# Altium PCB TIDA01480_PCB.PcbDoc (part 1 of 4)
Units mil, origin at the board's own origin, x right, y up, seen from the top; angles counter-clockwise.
Board outline 2500 x 3500 mil, 6 copper layers (Top Layer, GND Upper, Signal Layer 1, Signal Layer 2, GND Lower, Bottom Layer), stack 63.4 mil thick; 332 components, 140 nets, 983 pads, 692 vias.
Unrouted connection lines stored in the file: 17.
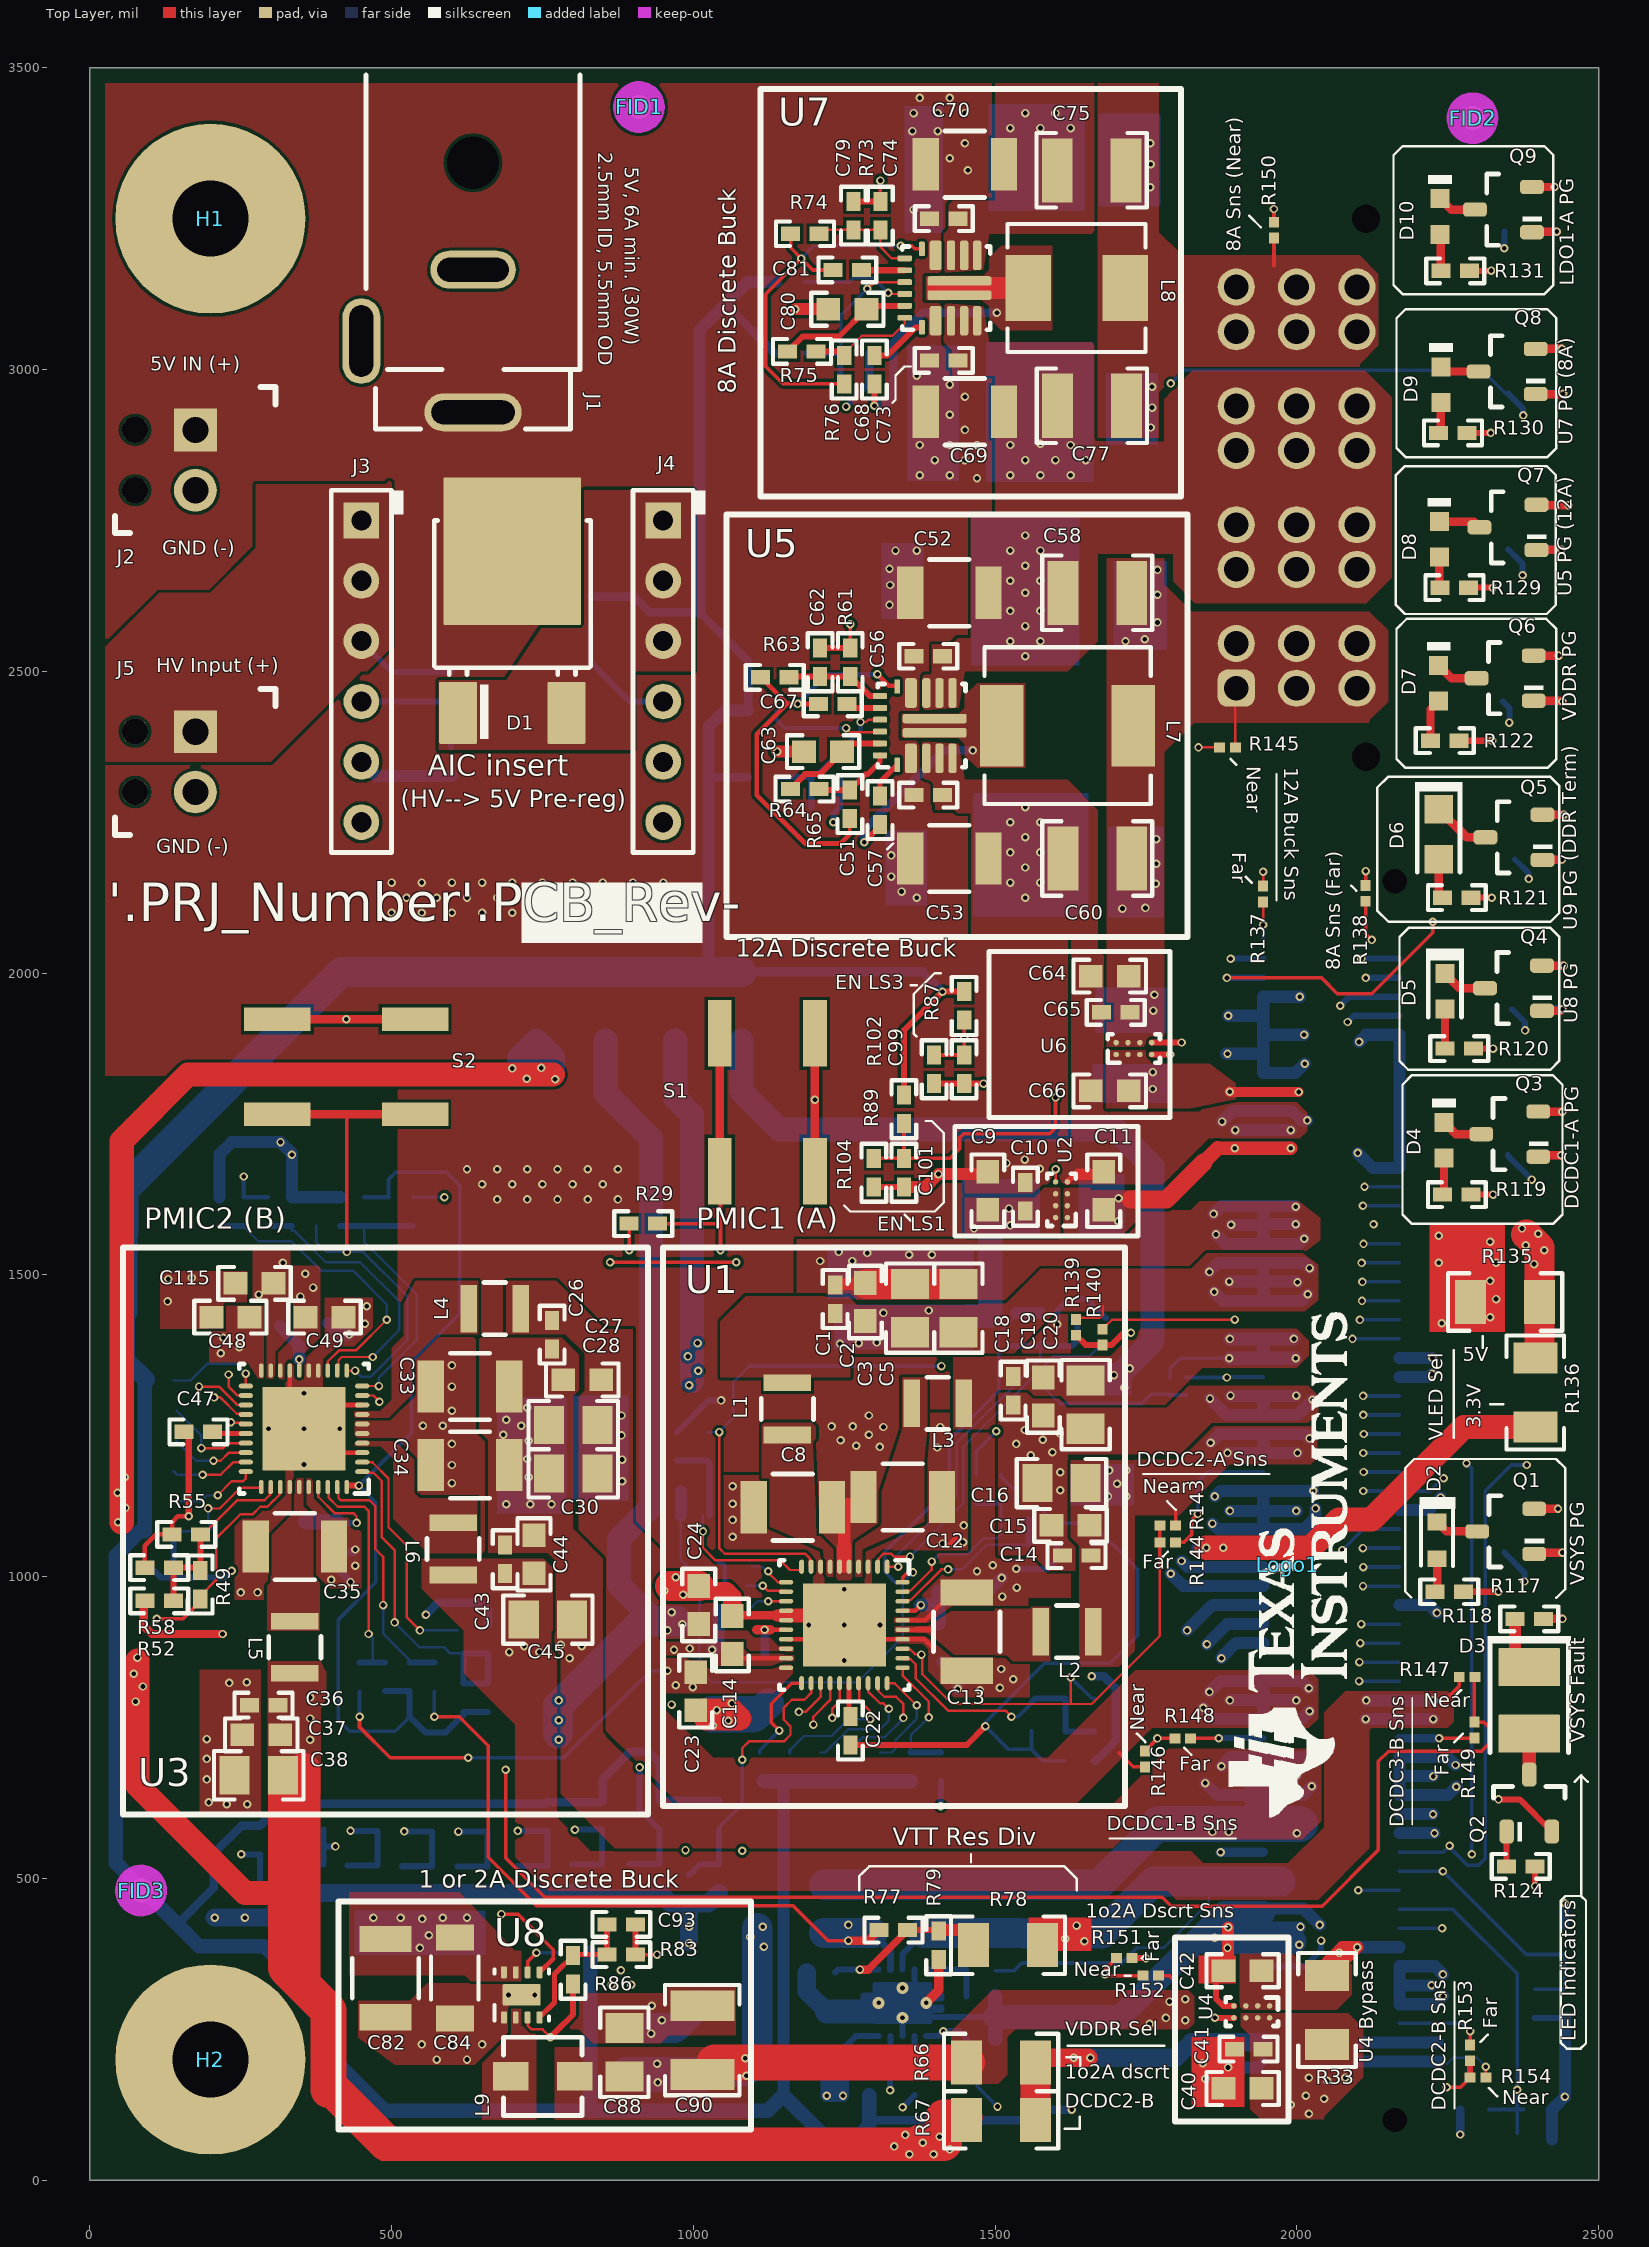
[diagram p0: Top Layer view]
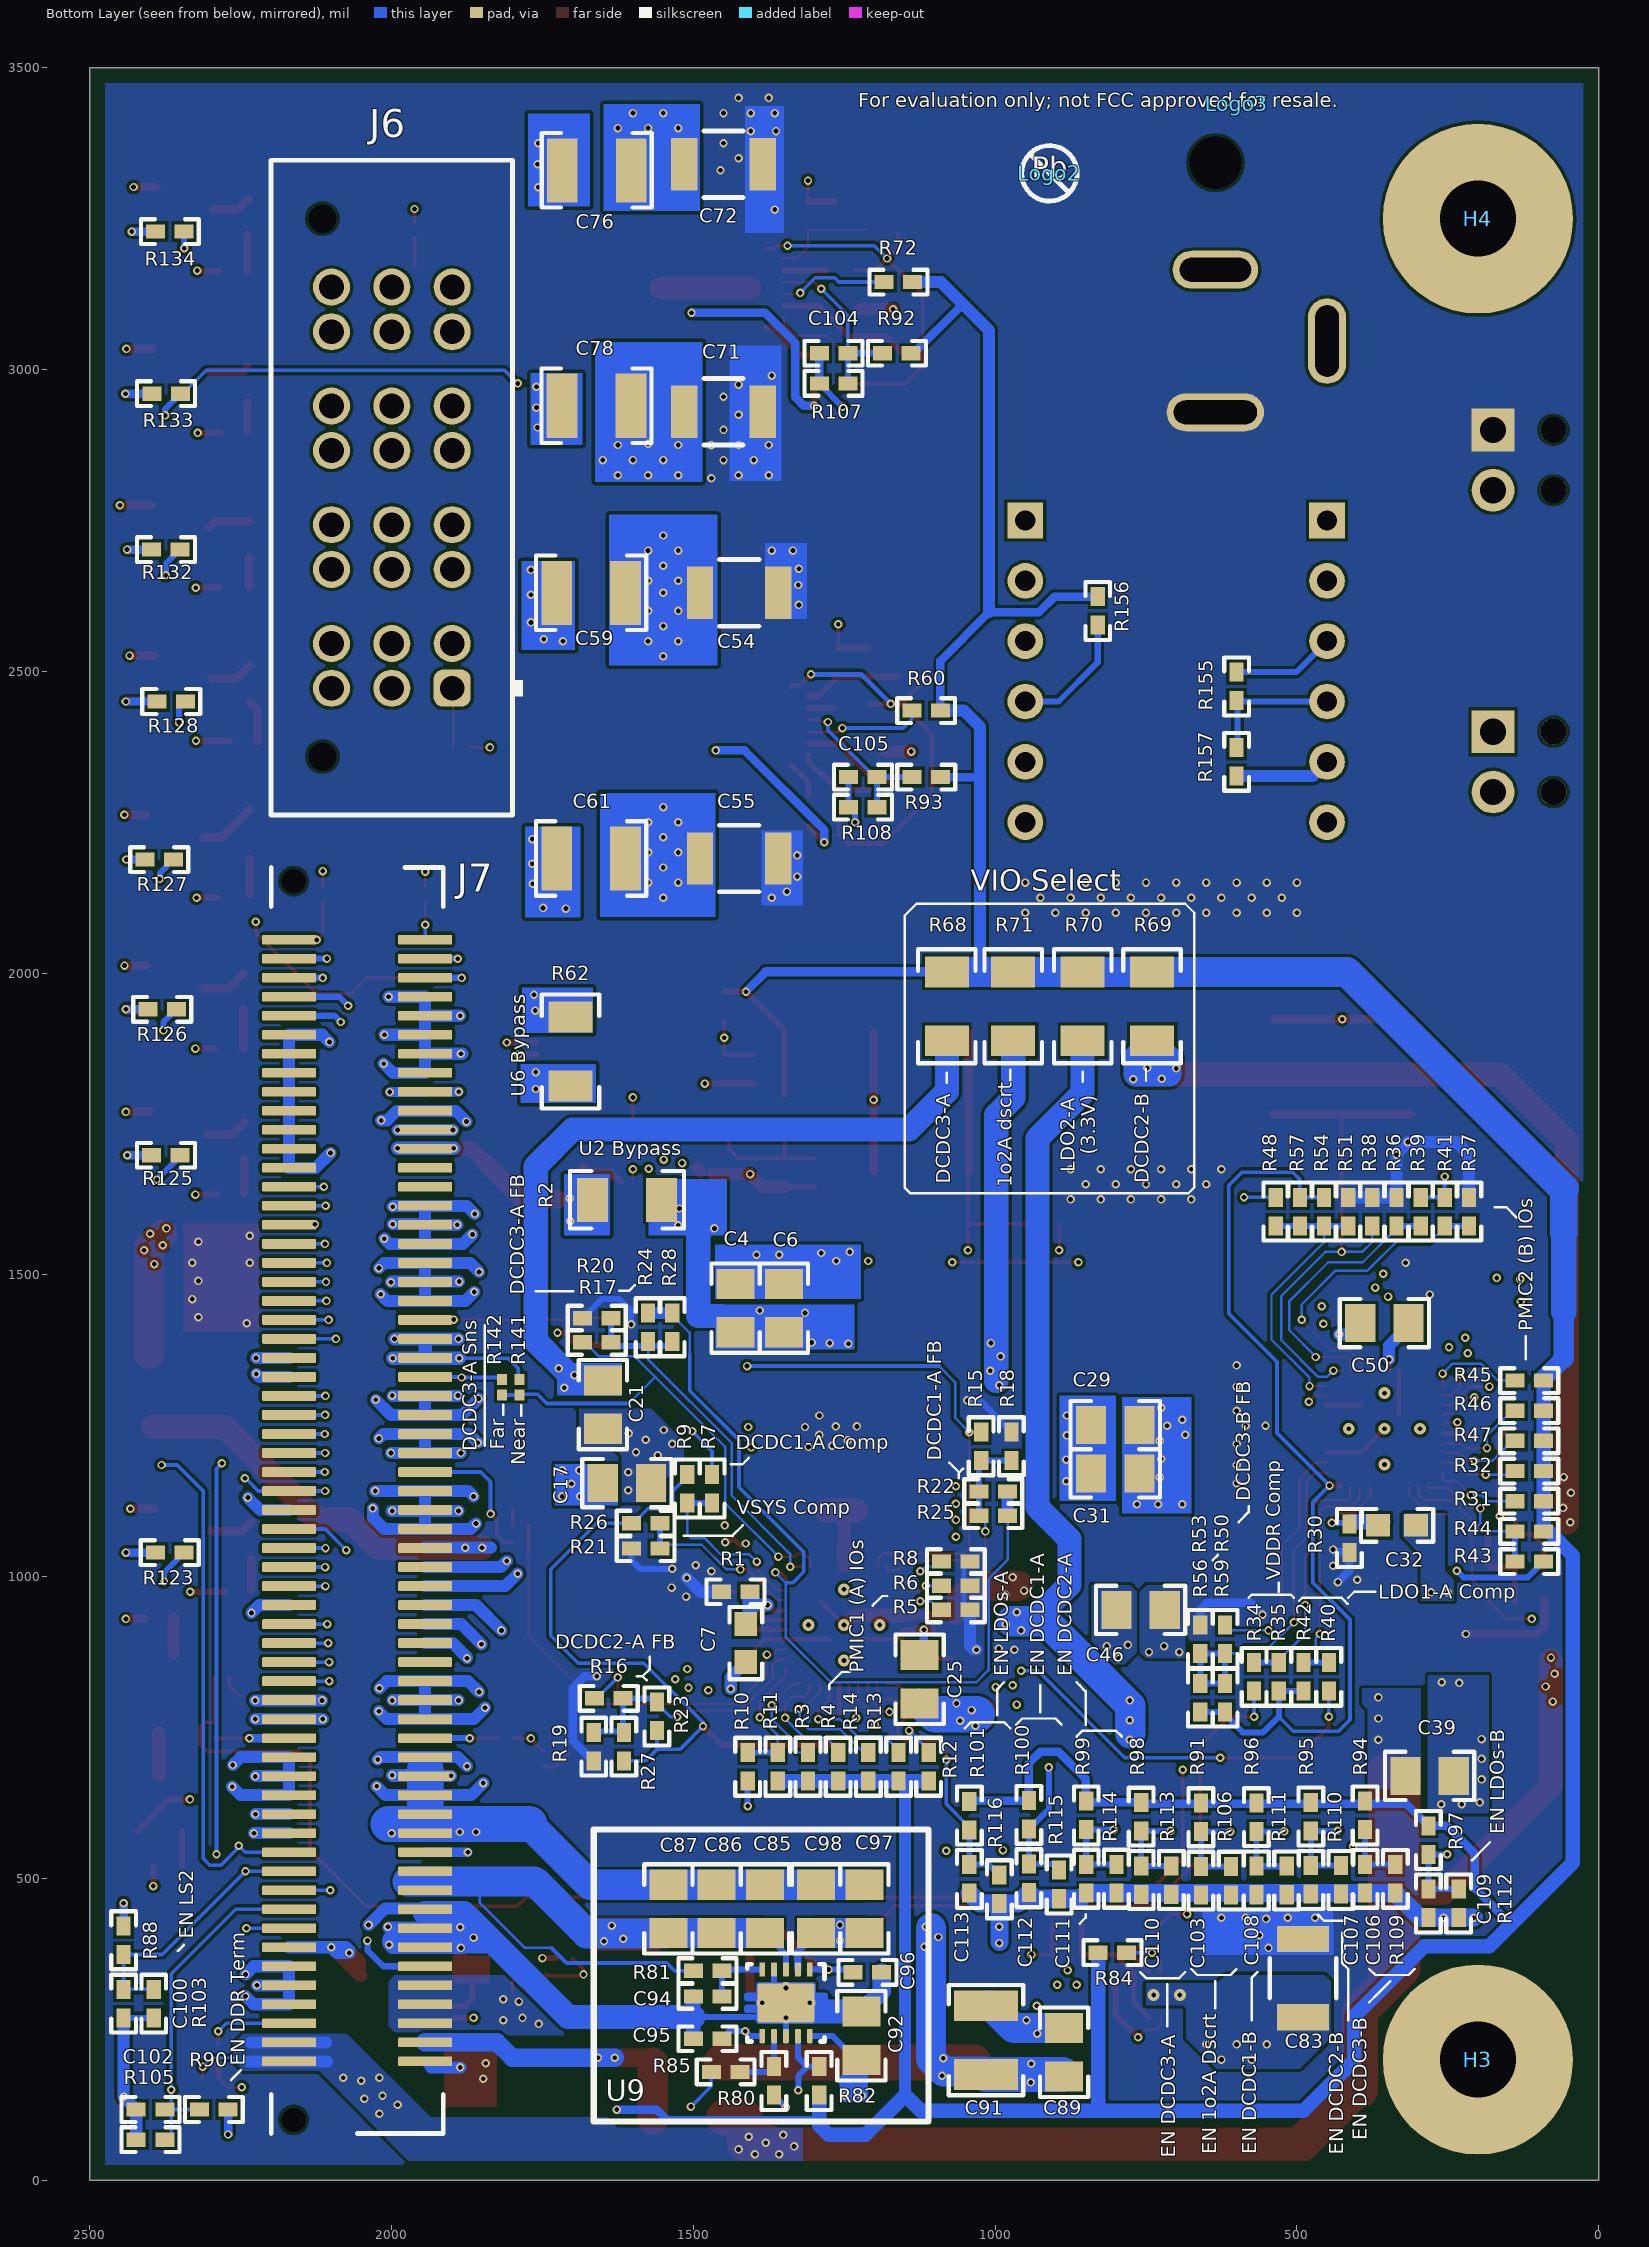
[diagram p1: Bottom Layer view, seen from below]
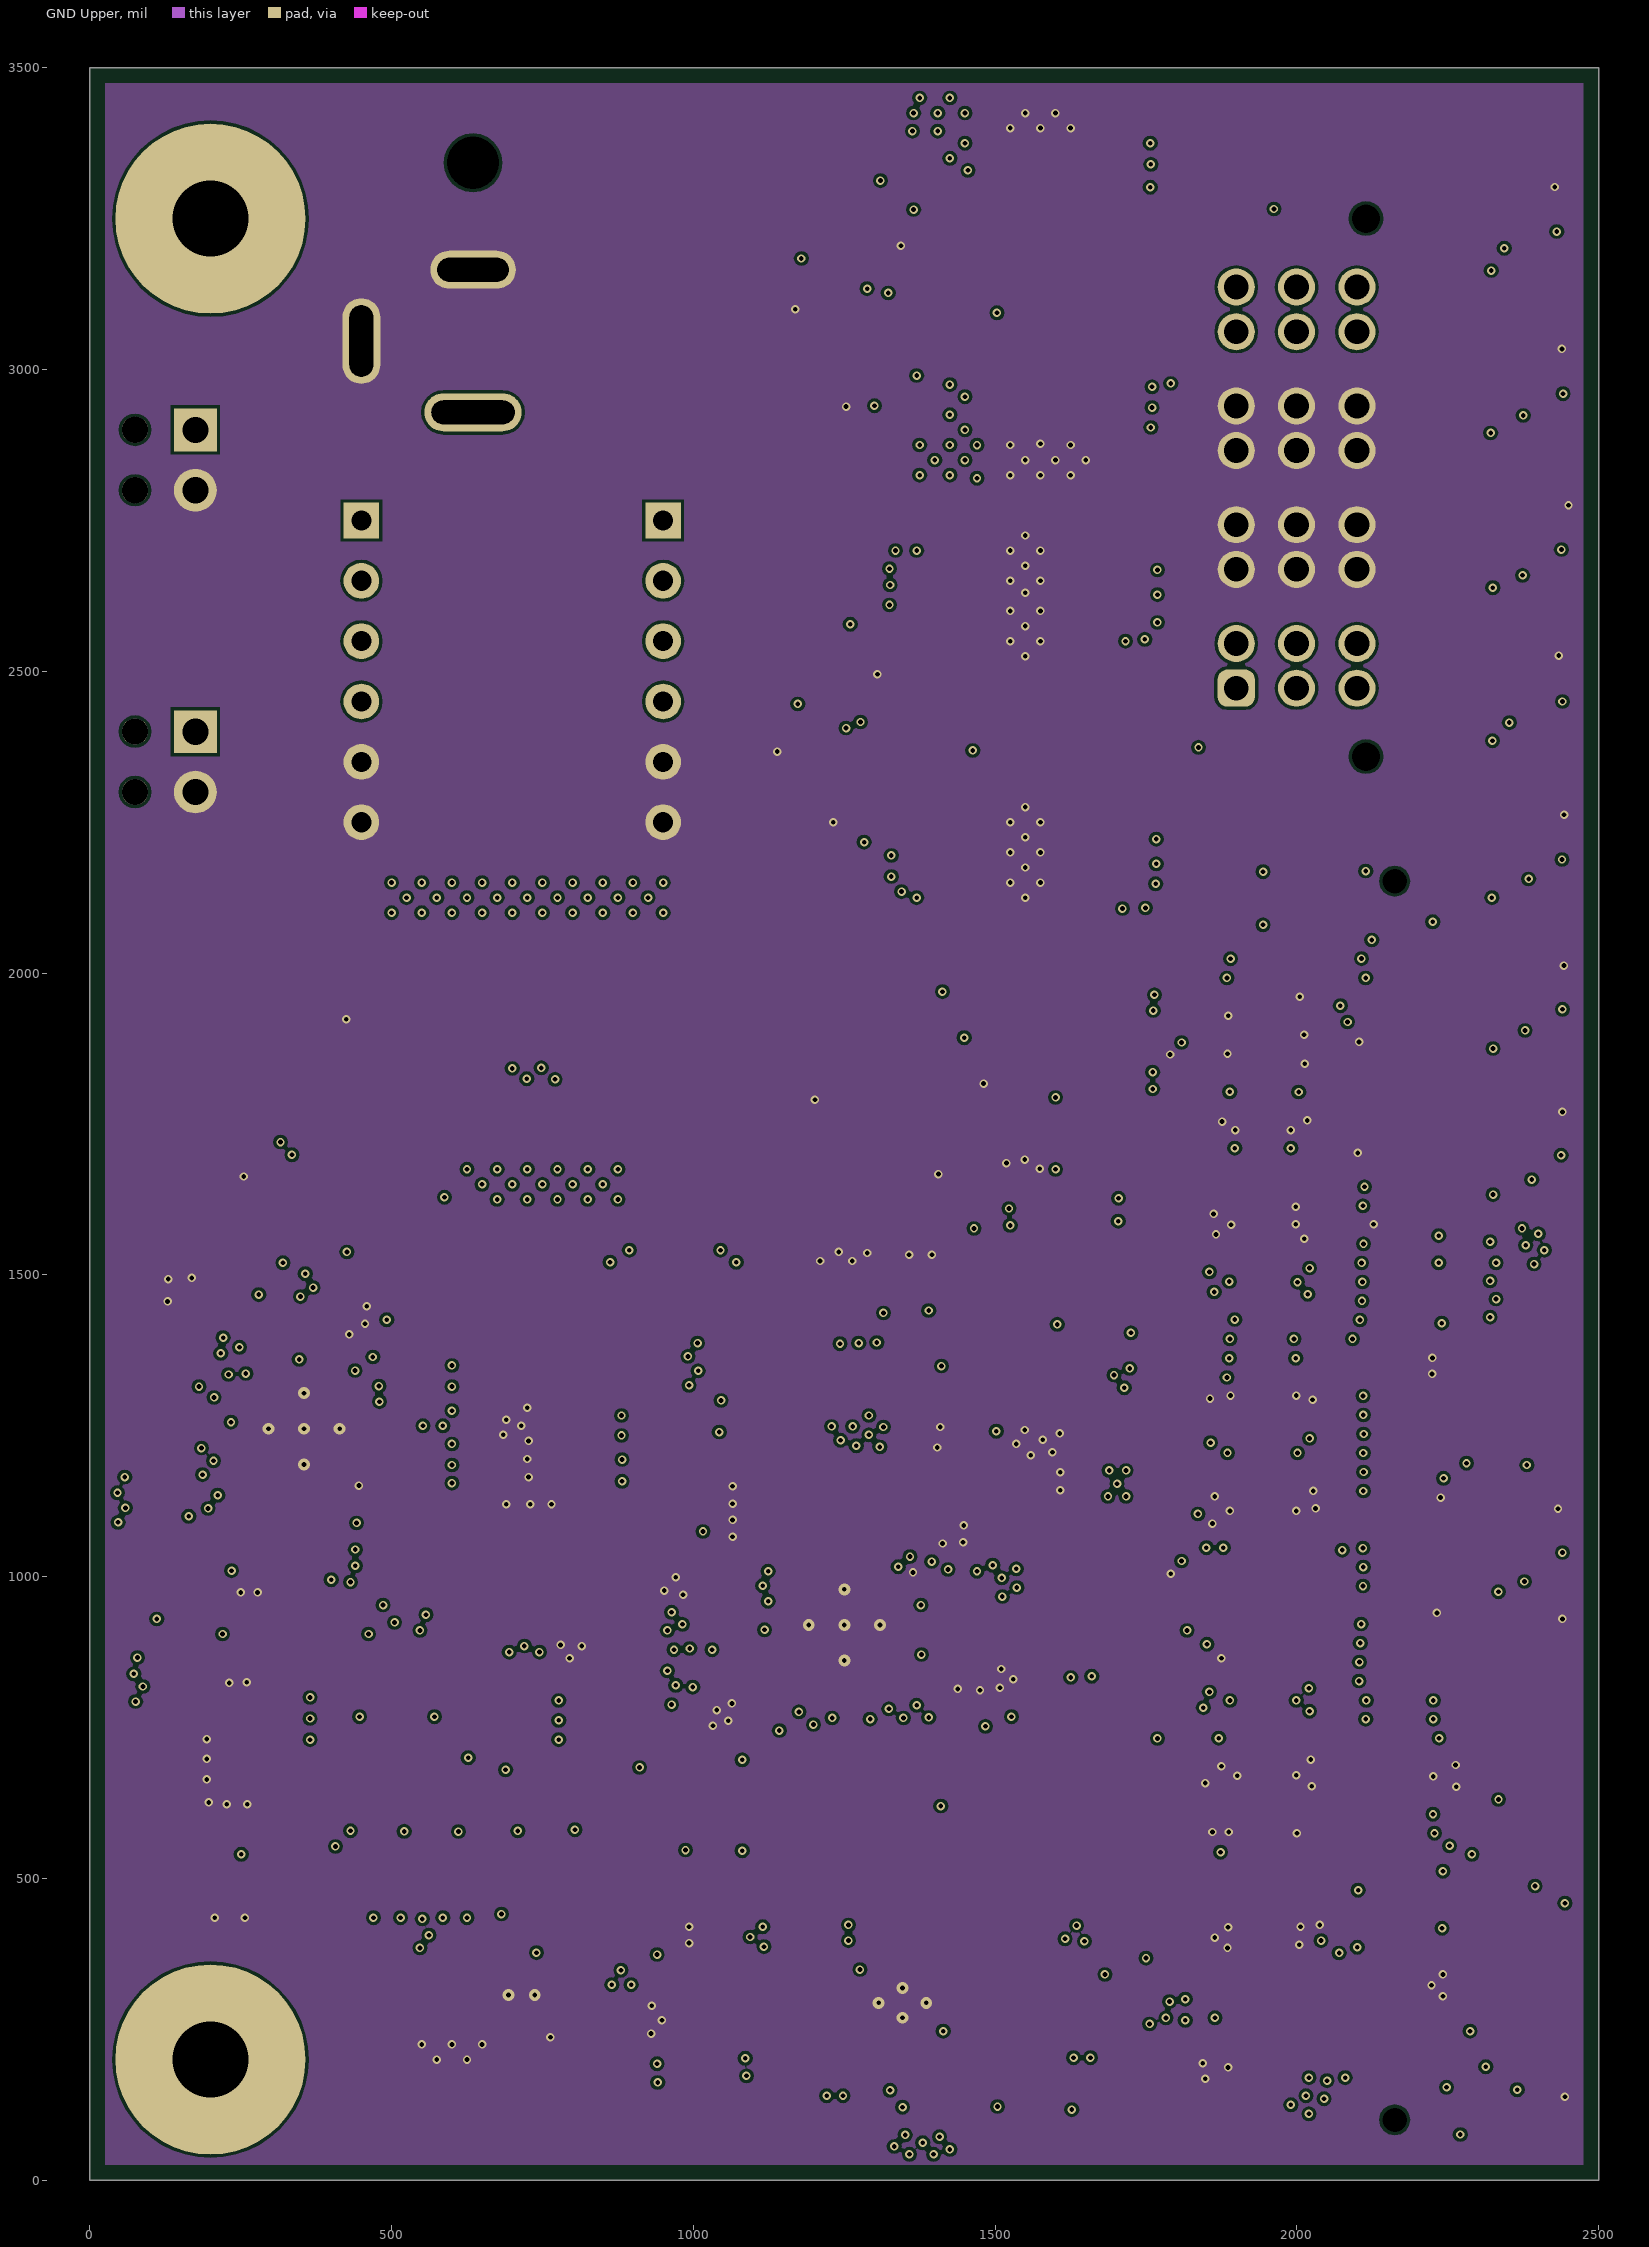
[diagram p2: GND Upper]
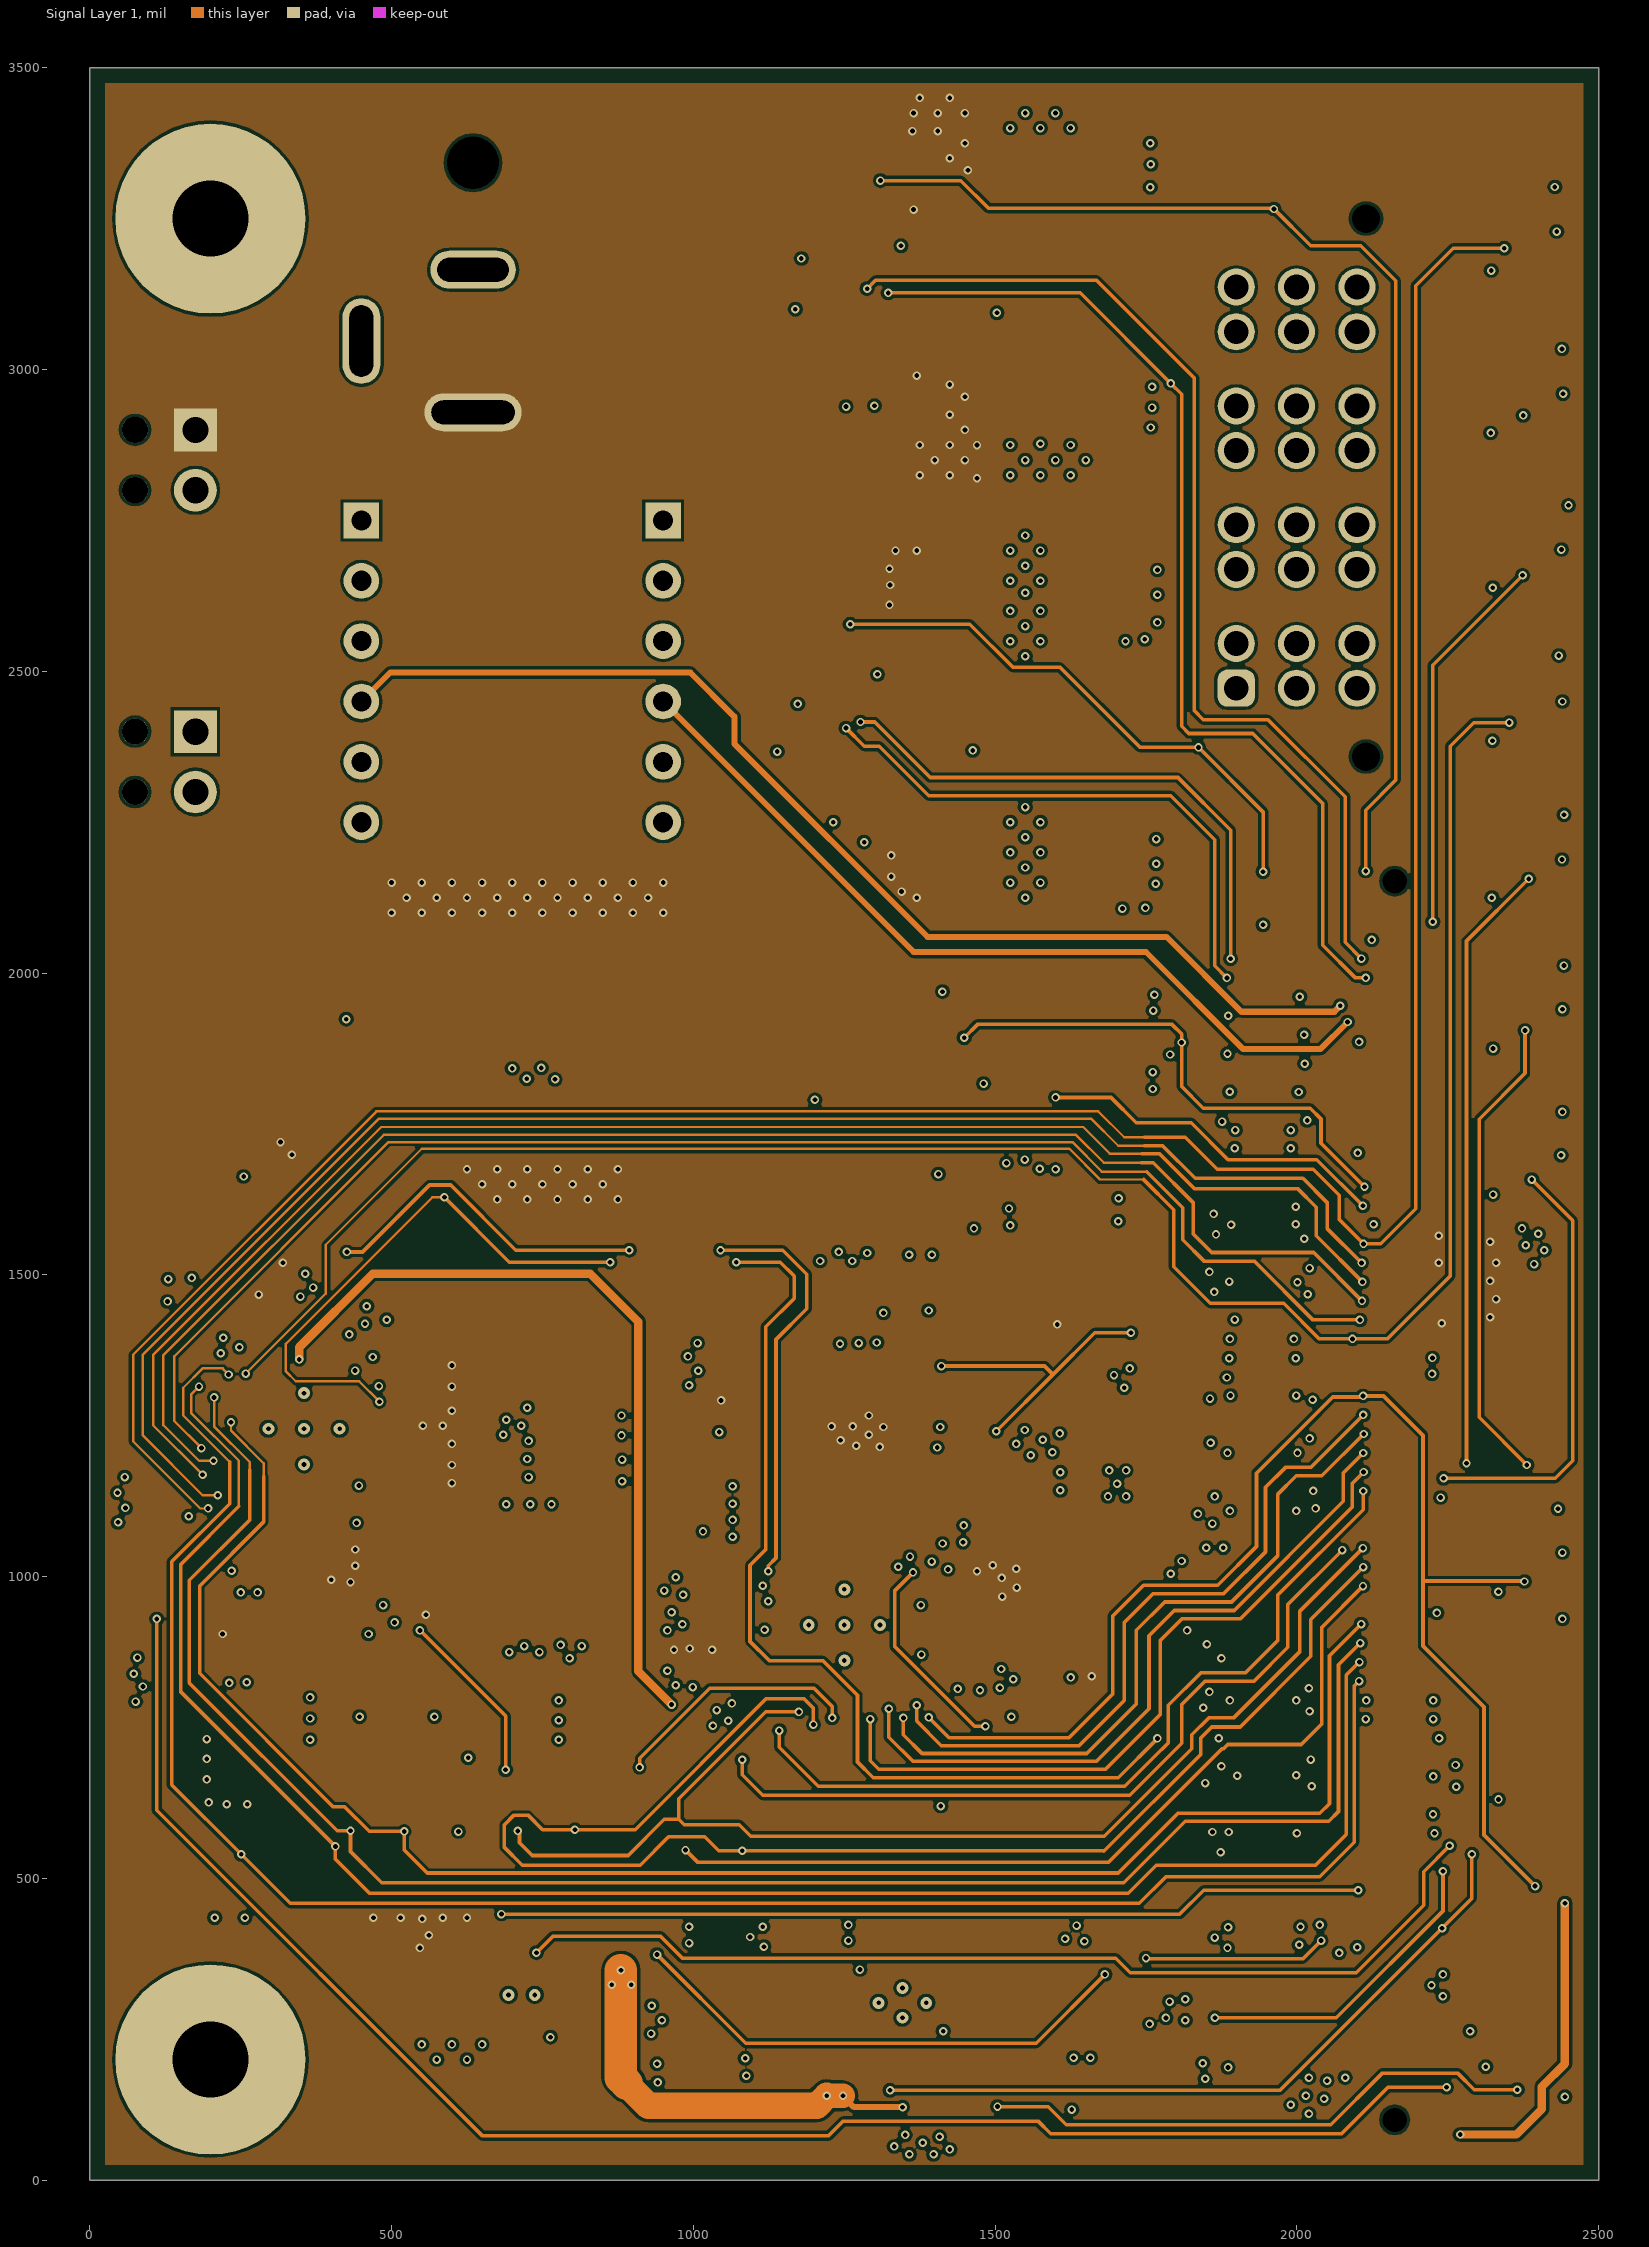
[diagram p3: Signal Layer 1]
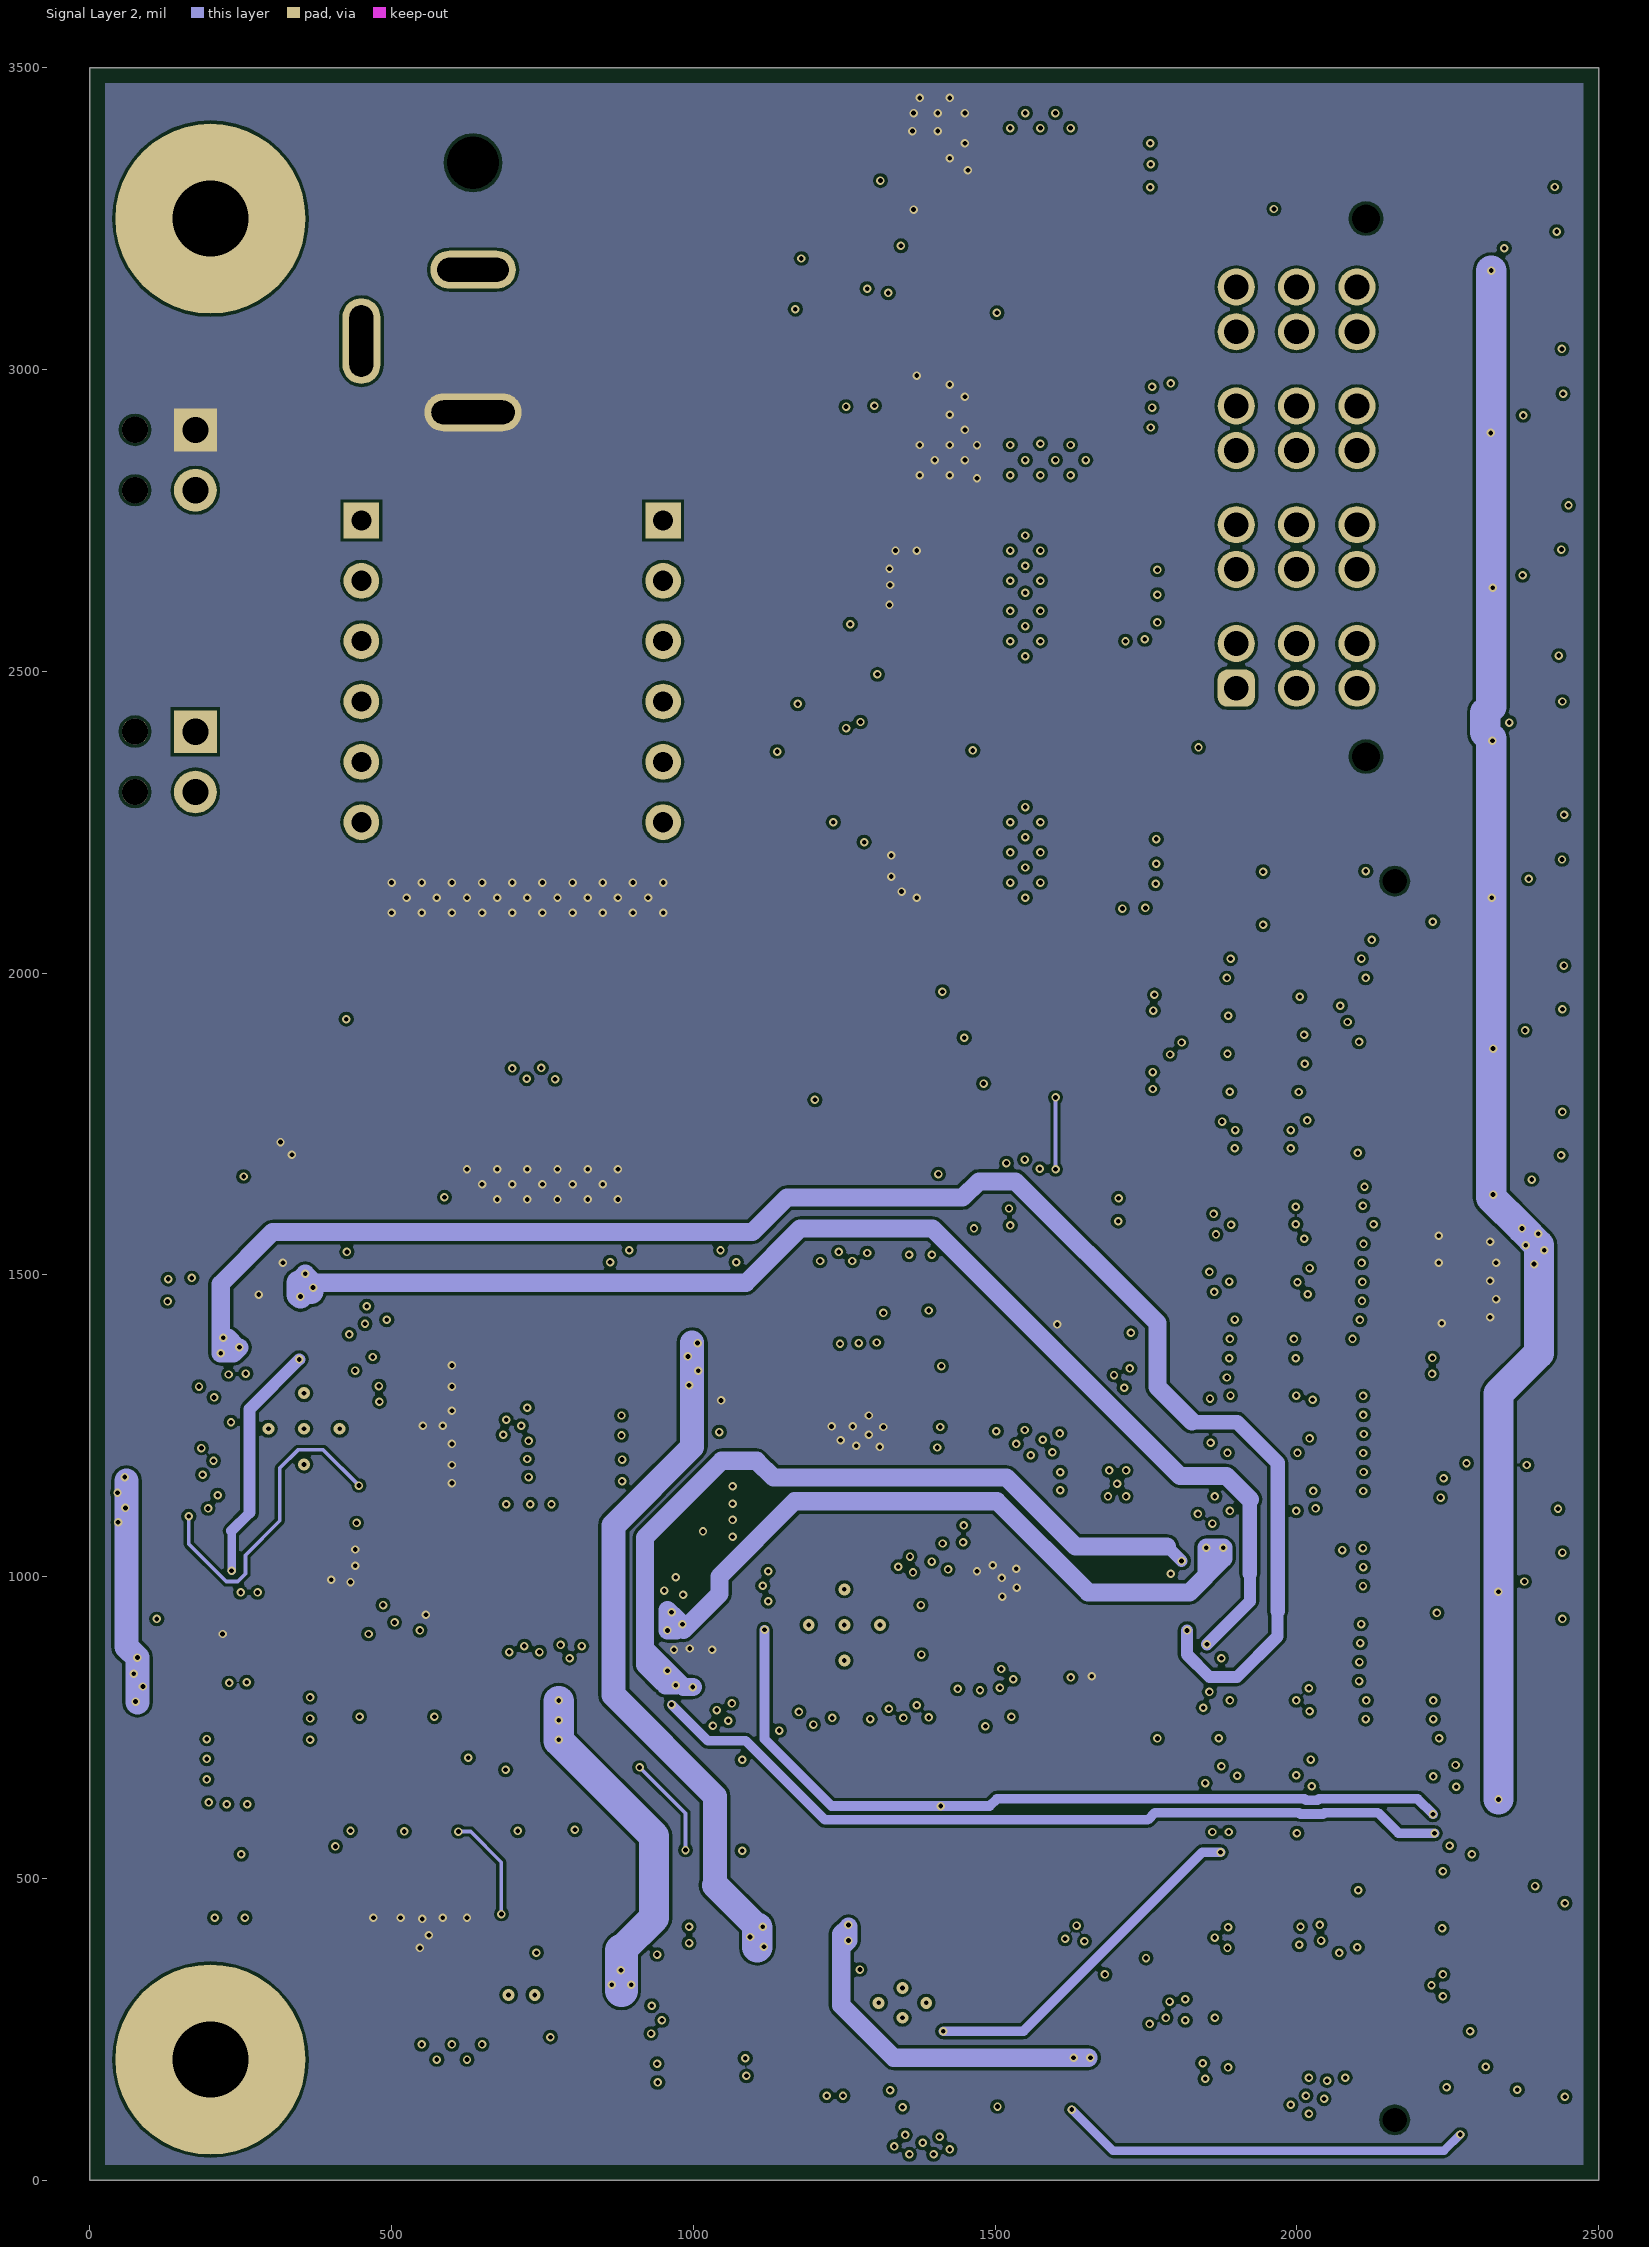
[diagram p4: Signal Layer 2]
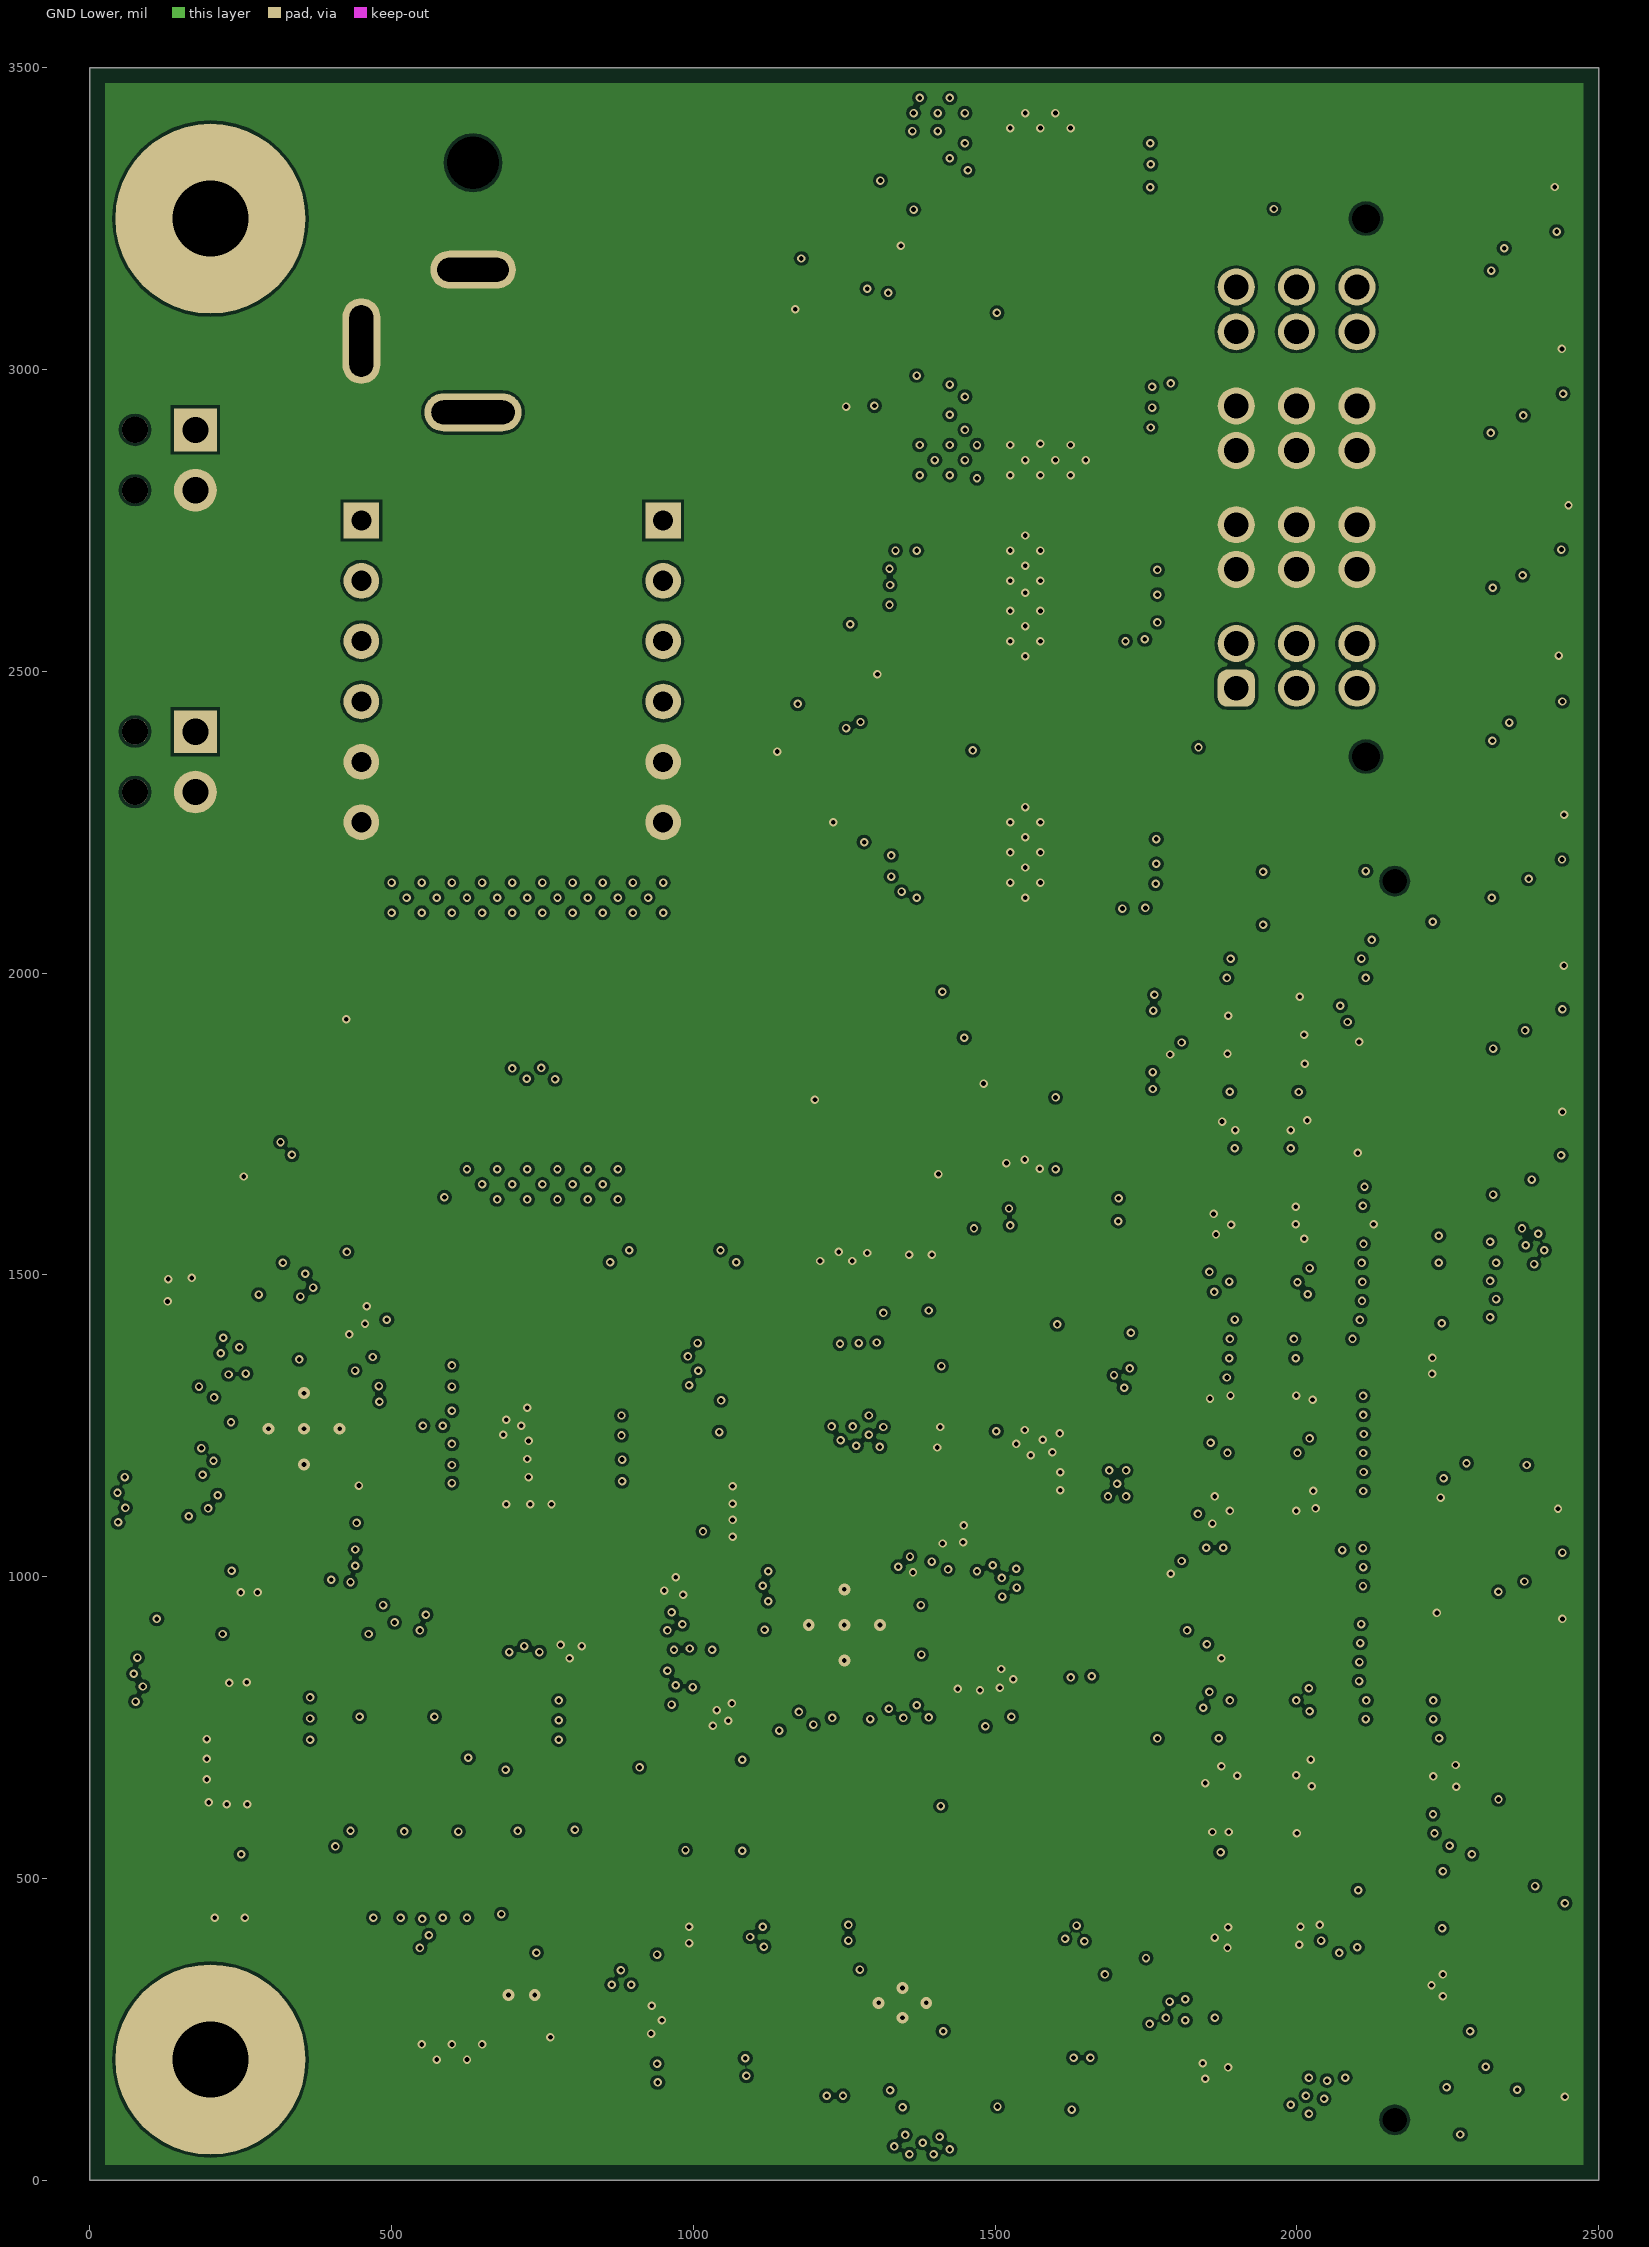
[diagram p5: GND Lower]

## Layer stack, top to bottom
Top Solder: solder mask 0.4, Solder Resist, Dk 3.5
Top Layer: signal copper 1.4
Dielectric 2: prepreg 9, FR-4, Dk 4.2
GND Upper: signal copper 1.4
Dielectric 4: core 14, FR-4, Dk 4.8
Signal Layer 1: signal copper 1.4
Dielectric1: prepreg 9, FR-4, Dk 4.2
Signal Layer 2: signal copper 1.4
Dielectric 5: core 14, FR-4, Dk 4.8
GND Lower: signal copper 1.4
Dielectric 3: prepreg 9, FR-4, Dk 4.2
Bottom Layer: signal copper 1.4
Bottom Solder: solder mask 0.4, Solder Resist, Dk 3.5

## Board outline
0,0 2500,0 2500,3500 0,3500

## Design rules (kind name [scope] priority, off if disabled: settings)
AcuteAngle [All] p1: minimum=4.50000000000000E+0001 checktracksonly=FALSE
AssemblyTestPointUsage [All] p1: valid=2
BoardOutlineClearance BoardOutlineClearance_MountingHoles [OnCopper and InComponentClass('Mounting Holes')] p1: gap=40 ignorepadtopadclearanceinfootprint=FALSE
BoardOutlineClearance BoardOutlineClearance_Poly [OnCopper and IsPoly] p2: gap=25 ignorepadtopadclearanceinfootprint=FALSE
BoardOutlineClearance [OnCopper and Not InComponentClass('Logo') and not InComponentClass('FiducialMark') and not InRegion(1000,500,4000,800) and not InPoly] p3: gap=30.11 ignorepadtopadclearanceinfootprint=FALSE
Clearance Clearance_Keepouts [((IsTrack Or IsArc) And Not InPoly) And IsFree and IsKeepOut vs ((IsTrack Or IsArc) And Not InPoly) And IsFree and IsKeepOut] p1: gap=0 ignorepadtopadclearanceinfootprint=FALSE
Clearance Clearance_Poly [InPolygon] p2: gap=5 ignorepadtopadclearanceinfootprint=FALSE except(0: Arc-Hole Track-Hole SMDPad-Hole THPad-Hole Via-Hole Fill-Hole Poly-Hole Region-Hole Text-Hole)
Clearance Clearance_FiducialMark [IsKeepOut and InComponentClass('FiducialMark') vs IsPad and InComponentClass('FiducialMark')] p3: gap=0 ignorepadtopadclearanceinfootprint=FALSE
Clearance [All] p4: gap=7.87 ignorepadtopadclearanceinfootprint=FALSE except(0: Arc-Hole Track-Hole SMDPad-Hole THPad-Hole Via-Hole Fill-Hole Poly-Hole Region-Hole Text-Hole; 0.11: THPad-THPad; 7: Arc-Arc Arc-Track Track-Track)
ComponentClearance ComponentClearance_MountingHoles_FiducialMarks [InComponentClass('Mounting Holes') vs InComponentClass('FiducialMark')] p1: gap=50 collisioncheckmode=3 verticalgap=10 showdistances=FALSE
ComponentClearance ComponentClearance_Shunt [InComponentClass('Header') vs InComponentClass('Shunt')] p2: gap=0 collisioncheckmode=3 verticalgap=0 showdistances=FALSE
ComponentClearance ComponentClearance_Logo [InComponentClass('Logo')] p3: gap=50 collisioncheckmode=3 verticalgap=10 showdistances=FALSE
ComponentClearance ComponentClearance_ScrewToNut [(HasFootprint('NY PMS 440 0025 PH')) vs (HasFootprint('Keystone_1902C'))] p4: gap=5 collisioncheckmode=3 verticalgap=10 showdistances=FALSE
ComponentClearance ComponentClearance_MountingHoles [InComponentClass('Mounting Holes')] p5: gap=100 collisioncheckmode=3 verticalgap=100000 showdistances=FALSE
ComponentClearance ComponentClearance_SmallPassives [HasFootprint('0201*') or HasFootprint('0402*') or HasFootprint('0508') or HasFootprint('0603*') or HasFootprint('0612') or HasFootprint('0805*') or HasFootprint('0815*') or HasFootprint('0830*') or HasFootprint('1206*') or HasFootprint('1210*') or HasFootprint('1808*') or HasFootprint('1812*') or HasFootprint('1825*') or HasFootprint('2010*') or HasFootprint('2220*') or HasFootprint('2225*') or HasFootprint('2512*') or HasFootprint('2728*') or HasFootprint('3518*') vs HasFootprint('0201*') or HasFootprint('0402*') or HasFootprint('0508') or HasFootprint('0603*') or HasFootprint('0612') or HasFootprint('0805*') or HasFootprint('0815*') or HasFootprint('0830*') or HasFootprint('1206*') or HasFootprint('1210*') or HasFootprint('1808*') or HasFootprint('1812*') or HasFootprint('1825*') or HasFootprint('2010*') or HasFootprint('2220*') or HasFootprint('2225*') or HasFootprint('2512*') or HasFootprint('2728*') or HasFootprint('3518*')] p6: gap=14.96 collisioncheckmode=3 verticalgap=10 showdistances=FALSE
ComponentClearance ComponentClearance_THtoSMT [IsThruComponent vs IsSMTComponent] p7: gap=40 collisioncheckmode=3 verticalgap=30 showdistances=FALSE
ComponentClearance ComponentClearance_THtoTH [IsThruComponent vs IsThruComponent] p8: gap=25.55 collisioncheckmode=3 verticalgap=30 showdistances=FALSE
ComponentClearance [All] p9: gap=30 collisioncheckmode=3 verticalgap=10 showdistances=FALSE
DiffPairsRouting [All] p1: maxlimit=100 minlimit=10 mostfreqgap=10 toplayer_minwidth=15 toplayer_maxwidth=15 toplayer_prefwidth=15 midlayer1_minwidth=15 midlayer1_maxwidth=15 midlayer1_prefwidth=15 midlayer2_minwidth=15 midlayer2_maxwidth=15 midlayer2_prefwidth=15 midlayer3_minwidth=15 midlayer3_maxwidth=15 midlayer3_prefwidth=15 midlayer4_minwidth=15 midlayer4_maxwidth=15 midlayer4_prefwidth=15 bottomlayer_minwidth=15 bottomlayer_maxwidth=15 bottomlayer_prefwidth=15 maxuncoupledlength=1000
FabricationTestPointUsage TestPointUsage [All] p1: valid=2 allowmultiple=FALSE
FabricationTestpoint Testpoint [All] p1: side=3 testpointundercomponent=TRUE minsize=40 maxsize=100 preferedsize=60 minholesize=0 maxholesize=40 preferedholesize=32 testpointgrid=1 allowsidetop=TRUE allowsidebottom=TRUE usegrid=TRUE gridtolerance=0.01
FanoutControl Fanout_LCC [IsLCC] p1: bgadir=Out bgaviamode=Centered fanoutstyle=Auto fanoutdirection=Alternating viagrid=1 // Fanout_LCC (Default Rule)
FanoutControl Fanout_BGA [IsBGA] p2: bgadir=Out bgaviamode=Centered fanoutstyle=Auto fanoutdirection=Alternating viagrid=1 // Fanout_BGA (Default Rule)
FanoutControl Fanout_Default [All] p4: bgadir=Out bgaviamode=Centered fanoutstyle=Auto fanoutdirection=Alternating viagrid=1 // Fanout_Default (Default Rule)
FanoutControl Fanout_Small [(CompPinCount < 5)] p5: bgadir=Out bgaviamode=Centered fanoutstyle=Auto fanoutdirection=OutThenIn viagrid=1 // Fanout_Small (Default Rule)
HoleSize [All] p1: absolutevalues=TRUE maxlimit=251 minlimit=7.87 maxpercent=80.000 minpercent=20.000
HoleToHoleClearance [All] p1: gap=17.5 allowstackedmicrovias=TRUE
MinimumAnnularRing MinimumAnnularRing_ThermalPadVias [IsVia and InAnyComponent] p1: minimumring=5.91
MinimumAnnularRing [All] p2: minimumring=3
MinimumSolderMaskSliver MinimumSolderMaskSliver_Logo [InComponentClass('Logo') vs InComponentClass('Logo')] p1: minsoldermaskwidth=0.7
MinimumSolderMaskSliver [All] p2: minsoldermaskwidth=3.94
PlaneConnect [All] p1: planeconnectstyle=Relief reliefexpansion=10 reliefentries=4 reliefconductorwidth=10 reliefairgap=10
PolygonConnect [All] p1: connectstyle=Direct reliefconductorwidth=10 reliefentries=4 polygonreliefangle="90 Angle" airgapwidth=10
RoutingVias ThermalPadVias [IsVia and InAnyComponent] p1: holewidth=7.87 width=19.68 viastyle="Through Hole" minholewidth=7.87 minwidth=19.68 maxholewidth=12.99 maxwidth=23.62
RoutingVias [All] p2: holewidth=18 width=10 viastyle="Through Hole" minholewidth=7.87 minwidth=14 maxholewidth=40 maxwidth=65
SilkToBoardRegionClearance [Not ((IsComment or IsDesignator) And (Hide <> 'False')) and not InRegion(1000,500,4000,800)] p1:
SilkToSilkClearance SilkToSilkClearance_Pb-FreeLogo [(HasFootprint('Pb-Free_Overlay_Medium') OR HasFootprint('Pb-Free_Overlay_Small')) vs (HasFootprint('Pb-Free_Overlay_Medium') OR HasFootprint('Pb-Free_Overlay_Small'))] p1: silktosilkclearance=0
SilkToSilkClearance [All] p2: silktosilkclearance=1.11
SilkToSolderMaskClearance SilkToComponentPadClearance [(IsPad or IsFill or IsRegion) and InAnycomponent] p1: minsilkscreentomaskgap=1.22 clearancetoexposedcopper=TRUE
SilkToSolderMaskClearance "Silk to Solder Mask Opening" [All] p2: minsilkscreentomaskgap=1.11 clearancetoexposedcopper=FALSE
SolderMaskExpansion [All] p1: expansion=1.97
Width [All] p1: maxlimit=100 minlimit=4 preferedwidth=10 checkconnectedcopper=TRUE
14 further rules are at their usual default settings.

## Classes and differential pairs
component class PMICs: 60 C1 C2 C3 C4 C5 C6 C7 C8 C9 C10 C11 C12 C13 C14 C15 C16 C17 C18 C19 C20 C21 C22 C23 C24 C25 C26 C27 C28 C29 C30 C31 C32 C33 C34 C35 C36 C37 C38 C39 C40 C41 C42 C43 C44 C45 C46 C47 C48 C49 C50 C114 C115 L1 L2 L3 L4 L5 L6 R1 R2 R3 R4 R5 R6 R7 R8 R9 R10 R11 R12 R13 R14 R15 R16 R17 R18 R19 R20 R21 R22 R23 R24 R25 R26 R27 R28 R29 R30 R31 R32 R33 R34 R35 R36 R37 R38 R39 R40 R41 R42 R43 R44 R45 R46 R47 R48 R49 R50 R51 R52 R53 R54 R55 R56 R57 R58 R59 S1 S2 U1 U2 U3 U4
component class IOs_and_LEDs: C99 C100 C101 C102 C103 C104 C105 C106 C107 C108 C109 C110 C111 C112 C113 D2 D3 D4 D5 D6 D7 D8 D9 D10 Q1 Q2 Q3 Q4 Q5 Q6 Q7 Q8 Q9 R87 R88 R89 R90 R91 R92 R93 R94 R95 R96 R97 R98 R99 R100 R101 R102 R103 R104 R105 R106 R107 R108 R109 R110 R111 R112 R113 R114 R115 R116 R117 R118 R119 R120 R121 R122 R123 R124 R125 R126 R127 R128 R129 R130 R131 R132 R133 R134 R135 R136
component class Header: J3 J4
component class Discrete_Rails: C51 C52 C53 C54 C55 C56 C57 C58 C59 C60 C61 C62 C63 C64 C65 C66 C67 C68 C69 C70 C71 C72 C73 C74 C75 C76 C77 C78 C79 C80 C81 C82 C83 C84 C85 C86 C87 C88 C89 C90 C91 C92 C93 C94 C95 C96 C97 C98 D1 J1 J2 J3 J4 J5 L7 L8 L9 R60 R61 R62 R63 R64 R65 R66 R67 R68 R69 R70 R71 R72 R73 R74 R75 R76 R77 R78 R79 R80 R81 R82 R83 R84 R85 R86 R155 R156 R157 U5 U6 U7 U8 U9
component class AssemblyNote: ZZ1 ZZ2 ZZ3 ZZ4
component class FiducialMark: FID1 FID2 FID3
component class Hardware: FID1 FID2 FID3 H1 H2 H3 H4 Logo1 Logo2 Logo3 ZZ1 ZZ2 ZZ3 ZZ4
component class Logo: Logo1
component class "Mounting Holes": H1 H2
component class Connector_to_FPGA: J6 J7 R137 R138 R139 R140 R141 R142 R143 R144 R145 R146 R147 R148 R149 R150 R151 R152 R153 R154

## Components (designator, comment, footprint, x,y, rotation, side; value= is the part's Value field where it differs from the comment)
C1 "GRM155R71A104KA01D" 0402 1235,1460 r90 top value=0.1uF
C2 "GRM188R71A225KE15D" 0603 1285,1455 r90 top value=2.2uF
C3 "C2012X7S1A226M125AC" 0805_HV 1359,1445 r90 top value=22uF
C4 "C2012X7S1A226M125AC" 0805_HV 1430,1445 r90 bottom value=22uF
C5 "C2012X7S1A226M125AC" 0805_HV 1439,1445 r90 top value=22uF
C6 "C2012X7S1A226M125AC" 0805_HV 1350,1445 r90 bottom value=22uF
C7 "885012106017" 0603 1413,890 r270 bottom value=1uF
C8 "C3225X7R1C226K250AC" 1210_280 1165,1115 r180 top value=22uF
C9 "GRM188R71A225KE15D" 0603 1488.07,1639.45 r90 top value=2.2uF
C10 "GRM155R61A105ME15D" 0402 1550,1629.45 r90 top value=1uF
C11 "JMK107BB7475MA-T" 0603 1680,1639.45 r90 top value=4.7uF
C12 "C3225X7R1C226K250AC" 1210_280 1347,1132 r0 top value=22uF
C13 "C3225X7R1C226K250AC" 1210_280 1453,909 r270 top value=22uF
C14 "GRM155R71A104KA01D" 0402 1635,1035 r180 top value=0.1uF
C15 "GRM188R71A225KE15D" 0603 1625,1085 r180 top value=2.2uF
C16 "C2012X7S1A226M125AC" 0805_HV 1610,1155 r180 top value=22uF
C17 "C2012X7S1A226M125AC" 0805_HV 1610,1155 r180 bottom value=22uF
C18 "GRM155R71A104KA01D" 0402 1530,1308.19 r270 top value=0.1uF
C19 "GRM188R71A225KE15D" 0603 1580,1298.35 r270 top value=2.2uF
C20 "C2012X7S1A226M125AC" 0805_HV 1650,1285 r270 top value=22uF
C21 "C2012X7S1A226M125AC" 0805_HV 1650,1285 r270 bottom value=22uF
C22 "GRM155R71H152KA01D" 0402 1260.22,745 r270 top value=1500pF
C23 "GRM188R71A225KE15D" 0603 1004,810 r270 top value=2.2uF
C24 "GRM188R71A225KE15D" 0603 1009,953 r90 top value=2.2uF
C25 "885012207025" 0805_HV 1125,830 r270 bottom value=4.7uF
C26 "GRM155R71A104KA01D" 0402 766,1401 r270 top value=0.1uF
C27 "GRM188R71A225KE15D" 0603 816,1326 r180 top value=2.2uF
C28 "C2012X7S1A226M125AC" 0805_HV 801,1251 r180 top value=22uF
C29 "C2012X7S1A226M125AC" 0805_HV 801,1251 r180 bottom value=22uF
C30 "C2012X7S1A226M125AC" 0805_HV 801,1171 r180 top value=22uF
C31 "C2012X7S1A226M125AC" 0805_HV 801,1171 r180 bottom value=22uF
C32 "885012106017" 0603 334,1085 r180 bottom value=1uF
C33 "C3225X7R1C226K250AC" 1210_280 630,1315 r0 top value=22uF
C34 "C3225X7R1C226K250AC" 1210_280 630,1185 r0 top value=22uF
C35 "C3225X7R1C226K250AC" 1210_280 340,1050 r180 top value=22uF
C36 "GRM155R71A104KA01D" 0402 288,787 r180 top value=0.1uF
C37 "GRM188R71A225KE15D" 0603 284,738 r180 top value=2.2uF
C38 "C2012X7S1A226M125AC" 0805_HV 280,671 r180 top value=22uF
C39 "C2012X7S1A226M125AC" 0805_HV 280,670 r180 bottom value=22uF
C40 "GRM188R71A225KE15D" 0603 1910,152.09 r180 top value=2.2uF
C41 "GRM155R61A105ME15D" 0402 1920,217.09 r180 top value=1uF
C42 "JMK107BB7475MA-T" 0603 1910,347.09 r180 top value=4.7uF
C43 "GRM155R71A104KA01D" 0402 688,1029 r90 top value=0.1uF
C44 "GRM188R71A225KE15D" 0603 736,1037 r90 top value=2.2uF
C45 "C2012X7S1A226M125AC" 0805_HV 759,929 r0 top value=22uF
C46 "C2012X7S1A226M125AC" 0805_HV 759,945 r0 bottom value=22uF
C47 "GRM155R71H152KA01D" 0402 180,1240 r180 top value=1500pF
C48 "GRM188R71A225KE15D" 0603 233,1430 r180 top value=2.2uF
C49 "GRM188R71A225KE15D" 0603 389,1430 r0 top value=2.2uF
C50 "885012207025" 0805_HV 355,1420 r0 bottom value=4.7uF
C51 "C1005X7R1E104M050BB" 0402 1309.27,2270 r270 top value=0.1uF
C52 "C3225X7R1C226K250AC" 1210_280 1424.27,2630 r0 top value=22uF
C53 "C3225X7R1C226K250AC" 1210_280 1424.27,2190 r0 top value=22uF
C54 "C3225X7R1C226K250AC" 1210_280 1424.27,2630 r0 bottom value=22uF
C55 "C3225X7R1C226K250AC" 1210_280 1424.27,2190 r0 bottom value=22uF
C56 "C1005X7R1E104M050BB" 0402 1389.27,2525 r0 top value=0.1uF
C57 "C1005X7R1E104M050BB" 0402 1389.27,2295 r0 top value=0.1uF
C58 "GRM32ER71A476KE15L" 1210_270 1669.27,2630 r180 top value=47uF
C59 "GRM32ER71A476KE15L" 1210_270 1669.27,2630 r180 bottom value=47uF
C60 "GRM32ER71A476KE15L" 1210_270 1669.27,2190 r180 top value=47uF
C61 "GRM32ER71A476KE15L" 1210_270 1669.27,2190 r180 bottom value=47uF
C62 "GRM1555C1E470JA01D" 0402 1210,2515 r270 top value=47pF
C63 "CGB3B1X5R1A475K055AC" 0603 1215,2367 r180 top value=4.7uF
C64 "GRM188R71A225KE15D" 0603 1690,1995 r180 top value=2.2uF
C65 "GRM155R61A105ME15D" 0402 1700,1935 r180 top value=1uF
C66 "JMK107BB7475MA-T" 0603 1690,1805 r180 top value=4.7uF
C67 "C1005X7R1H473K050BB" 0402 1231,2446 r180 top value=0.047uF
C68 "C1005X7R1E104M050BB" 0402 1300,3000 r270 top value=0.1uF
C69 "C3225X7R1C226K250AC" 1210_280 1450,2930 r0 top value=22uF
C70 "C3225X7R1C226K250AC" 1210_280 1450,3340 r0 top value=22uF
C71 "C3225X7R1C226K250AC" 1210_280 1450,2930 r0 bottom value=22uF
C72 "C3225X7R1C226K250AC" 1210_280 1450,3340 r0 bottom value=22uF
C73 "C1005X7R1E104M050BB" 0402 1415,3015 r0 top value=0.1uF
C74 "C1005X7R1E104M050BB" 0402 1415,3250 r0 top value=0.1uF
C75 "GRM32ER71A476KE15L" 1210_270 1660,3330 r180 top value=47uF
C76 "GRM32ER71A476KE15L" 1210_270 1660,3330 r180 bottom value=47uF
C77 "GRM32ER71A476KE15L" 1210_270 1660.32,2940 r180 top value=47uF
C78 "GRM32ER71A476KE15L" 1210_270 1660.32,2940 r180 bottom value=47uF
C79 "GRM1555C1E470JA01D" 0402 1265.22,3255 r270 top value=47pF
C80 "CGB3B1X5R1A475K055AC" 0603 1255.22,3100 r180 top value=4.7uF
C81 "C1005X7R1H473K050BB" 0402 1255.22,3165 r180 top value=0.047uF
C82 "C3225X7R1C226K250AC" 1210_280 490,335 r270 top value=22uF
C83 "C3225X7R1C226K250AC" 1210_280 490,335 r270 bottom value=22uF
C84 "C3216X7R1E106M160AE" 1206_190 605,335 r270 top value=10uF
C85 "GRM21BR70J106KE76L" 0805_HV 1381.48,449.45 r90 bottom value=10uF
C86 "GRM21BR70J106KE76L" 0805_HV 1461.48,449.45 r90 bottom value=10uF
C87 "GRM21BR70J106KE76L" 0805_HV 1541.48,449.45 r90 bottom value=10uF
C88 "C2012X7S1A226M125AC" 0805_HV 885.63,212.09 r90 top value=22uF
C89 "C2012X7S1A226M125AC" 0805_HV 885.63,212.09 r90 bottom value=22uF
C90 "GRM32ER71A476KE15L" 1210_270 1015,232.09 r90 top value=47uF
C91 "GRM32ER71A476KE15L" 1210_270 1015,232.09 r90 bottom value=47uF
C92 "GRM21BR60J475KA11L" 0805_HV 1221.48,239.45 r90 bottom value=4.7uF
C93 "GCM1555C1H220JA16D" 0402 880.79,423.87 r180 top value=22pF
C94 "GRM1555C1H100JA01D" 0402 1476.48,304.45 r0 bottom value=10pF
C95 "GRM155R71A104KA01D" 0402 1476.48,234.45 r0 bottom value=0.1uF
C96 "C1005X7R1H102M050BE" 0402 1211.48,344.45 r180 bottom value=1000pF
C97 "GRM21BR70J106KE76L" 0805_HV 1216.48,449.45 r90 bottom value=10uF
C98 "GRM21BR70J106KE76L" 0805_HV 1296.48,449.45 r90 bottom value=10uF
C99 "GRM1555C1E911JA01D" 0402 1448.79,1840.63 r270 top value=910pF
C100 "GRM1555C1E911JA01D" 0402 2444,292.62 r270 bottom value=910pF
C101 "GRM1555C1E911JA01D" 0402 1349,1669.37 r270 top value=910pF
C102 "GRM1555C1E911JA01D" 0402 2399.37,117.21 r0 bottom value=910pF
C103 "GRM1555C1E511JA01D" 0402 659,496.38 r270 bottom value=510pF
C104 "GRM1555C1H101JA01D" 0402 1267.72,3027 r0 bottom value=100pF
C105 "GRM1555C1H100FA01D" 0402 1219,2324.83 r0 bottom value=10pF
C106 "GRM1555C1E511JA01D" 0402 387,499.37 r270 bottom value=510pF
C107 "GRM1555C1E511JA01D" 0402 477,497.62 r270 bottom value=510pF
C108 "GRM1555C1H101JA01D" 0402 567,496.62 r270 bottom value=100pF
C109 "GRM1555C1H100FA01D" 0402 282,458.62 r270 bottom value=10pF
C110 "GRM1555C1H100FA01D" 0402 758,497.38 r270 bottom value=10pF
C111 "GRM1555C1H101JA01D" 0402 849,499.38 r270 bottom value=100pF
C112 "GRM1555C1H101JA01D" 0402 944,500.38 r270 bottom value=100pF
C113 "GRM1555C1H100FA01D" 0402 1042.65,499.22 r270 bottom value=10pF
C114 "885012106017" 0603 1064.53,903.47 r90 top value=1uF
C115 "885012106017" 0603 273,1486 r180 top value=1uF
D1 "12CWQ04FNPBF" DPAK 700,2565 r90 top value=40V
D2 "LNJ037X8ARA" LNJ037X8_WHITE 2232.4,1060 r270 top value="Cool White"
D3 "VLMR334BACB-GS08" VLMR334_Red 2385,795 r90 top value=Red
D4 "LTST-C190KGKT" LED_LTST-C190_G 2243.76,1723.21 r90 top value=Green
D5 "LTST-C190KFKT" LED_LTST-C190 2245,1970 r90 top value=Orange
D6 "LTST-C170KSKT" LED_LTST-C170 2235,2230 r90 top value=Yellow
D7 "LTST-C190KGKT" LED_LTST-C190_G 2235,2480 r90 top value=Green
D8 "LTST-C190KGKT" LED_LTST-C190_G 2236.04,2718.58 r90 top value=Green
D9 "LTST-C190KGKT" LED_LTST-C190_G 2238.62,2975 r90 top value=Green
D10 "LTST-C190KGKT" LED_LTST-C190_G 2237.24,3253.52 r90 top value=Green
FID1 "Fiducial" Fiducial10-20 910,3435 r0 top
FID2 "Fiducial" Fiducial10-20 2290.98,3416.48 r0 top
FID3 "Fiducial" Fiducial10-20 85,480 r0 top
H1 "NY PMS 440 0025 PH" "NY PMS 440 0025 PH" 200,3250 r0 top locked
H2 "NY PMS 440 0025 PH" "NY PMS 440 0025 PH" 200,200 r0 top locked
H3 "1902C" Keystone_1902C 200.36,200 r180 bottom locked
H4 "1902C" Keystone_1902C 200.36,3250 r180 bottom locked
J1 "PJ-058B" CUI_PJ-058B 635,3500 r180 top
J2 "1725656" CONN_1725656 175,2850 r270 top
J3 "800-10-006-10-001000" Mill-Max_800-10-006-10-001000 450,2500 r270 top
J4 "800-10-006-10-001000" Mill-Max_800-10-006-10-001000 950,2500 r270 top
J5 "1725656" CONN_1725656 175,2350 r270 top
J6 "MPS-04-7.70-01-L-V" Samtec_MPS-04-7_70-01-x-V 2007,2804.33 r0 bottom
J7 "BSE-060-01-L-D-A" Samtec_BSE-060-01-L-D-A 2057,1126.18 r90 bottom
L1 "TFM252012ALMA2R2MTAA" TFM252012 1156,1278 r90 top value=2.2uH
L2 "TFM252012ALMA2R2MTAA" TFM252012 1619,909 r0 top value=2.2uH
L3 "TFM252012ALMA2R2MTAA" TFM252012 1405,1287 r0 top value=2.2uH
L4 "TFM252012ALMA2R2MTAA" TFM252012 671,1444 r0 top value=2.2uH
L5 "TFM252012ALMA2R2MTAA" TFM252012 340,883 r270 top value=2.2uH
L6 "TFM252012ALMA2R2MTAA" TFM252012 602,1046 r270 top value=2.2uH
L7 "IHLP2525CZERR47M01" IHLP-2525CZ 1620,2410 r0 top value=470nH
L8 "IHLP2020BZERR47M01" IHLP-2020BZ 1635,3135 r0 top value=470nH
L9 "IHLP1212ABER1R0M11" IHLP-1212AB 750.63,172.09 r0 top value=1uH
Logo1 "Texas Instruments" TI_Stacked_Overlay_Small 1985,1020 r90 top
Logo2 "Pb-Free Symbol" Pb-Free_Overlay_Small 910,3325 r180 bottom
Logo3 "FCC disclaimer" FCC_disclaimer 600,3440 r180 bottom
Q1 "2N7002-7-F" SOT-23 2345.98,1075 r180 top value=60V
Q2 "BSS84-7-F" SOT-23 2385,625 r90 top value=-50V
Q3 "2N7002-7-F" SOT-23 2352.66,1733.21 r180 top value=60V
Q4 "2N7002-7-F" SOT-23 2358.9,1975 r180 top value=60V
Q5 "2N7002-7-F" SOT-23 2359.68,2225 r180 top value=60V
Q6 "2N7002-7-F" SOT-23 2345,2488.6 r180 top value=60V
Q7 "2N7002-7-F" SOT-23 2349.74,2738.58 r180 top value=60V
Q8 "2N7002-7-F" SOT-23 2348.31,2996.79 r180 top value=60V
Q9 "2N7002-7-F" SOT-23 2342.24,3265 r180 top value=60V
R1 "CRCW040210R0FKED" 0402 1430,975 r180 bottom value=10.0
R2 "CRCW12060000Z0EA" 1206 1610,1624.45 r0 bottom value=0
R3 "CRCW04025K60JNED" 0402 1310,685 r270 bottom value=5.6k
R4 "CRCW04025K60JNED" 0402 1260,685 r270 bottom value=5.6k
R5 "CRCW040268R0JNED" 0402 1065,945 r180 bottom value=68
R6 "CRCW040268R0JNED" 0402 1065,985 r180 bottom value=68
R7 "CRCW040210K2FKED" 0402 1469,1146 r90 bottom value=10.2k
R8 "CRCW0402100KJNED" 0402 1065,1025 r180 bottom value=100k
R9 "RG1005P-104-B-T5" 0402 1510,1146 r270 bottom value=100k
R10 "CRCW0402100KJNED" 0402 1410,685 r90 bottom value=100k
R11 "CRCW040210K0JNED" 0402 1360,685 r270 bottom value=10k
R12 "CRCW040210K0JNED" 0402 1110,685 r270 bottom value=10k
R13 "CRCW040210K0JNED" 0402 1160,685 r270 bottom value=10k
R14 "CRCW040210K0JNED" 0402 1210,685 r270 bottom value=10k
R15 "RG1005P-104-B-T5" 0402 1023,1216 r90 bottom value=100k
R16 "CRCW0402200KFKED" 0402 1640.22,798.38 r0 bottom value=200k
R17 "CRCW0402226KFKED" 0402 1660,1388.35 r0 bottom value=226k
R18 "CRCW040268R0JNED" 0402 973,1216 r90 bottom value=68
R19 "CRCW040268R0JNED" 0402 1665,718.38 r270 bottom value=68
R20 "CRCW040268R0JNED" 0402 1660,1428.35 r0 bottom value=68
R21 "CRCW0402316KFKED" 0402 1579,1046.54 r0 bottom value=316k
R22 "RG1005P-104-B-T5" 0402 1003,1141 r0 bottom value=100k
R23 "RG1005P-104-B-T5" 0402 1560.22,768.38 r90 bottom value=100k
R24 "ERJ-2RKF4992X" 0402 1575,1413.35 r270 bottom value=49.9k
R25 "CRCW040268R0JNED" 0402 1003,1101 r0 bottom value=68
R26 "RG1005P-104-B-T5" 0402 1579,1088.54 r180 bottom value=100k
R27 "CRCW040268R0JNED" 0402 1615,718.38 r90 bottom value=68
R28 "CRCW040268R0JNED" 0402 1535,1413.35 r270 bottom value=68
R29 "CRCW04020000Z0ED" 0402 917,1585 r0 top value=0
R30 "CRCW040210R0FKED" 0402 413,1064 r90 bottom value=10.0
R31 "CRCW04025K60JNED" 0402 115,1125 r180 bottom value=5.6k
R32 "CRCW04025K60JNED" 0402 115,1175 r180 bottom value=5.6k
R33 "CRCW12060000Z0EA" 1206 2050,282.09 r90 top value=0
R34 "CRCW040224K9FKED" 0402 571,834 r270 bottom value=24.9k
R35 "RG1005P-104-B-T5" 0402 530,834 r90 bottom value=100k
R36 "CRCW040268R0JNED" 0402 335,1605 r90 bottom value=68
R37 "CRCW040268R0JNED" 0402 215,1605 r90 bottom value=68
R38 "CRCW0402100KJNED" 0402 375,1605 r90 bottom value=100k
R39 "CRCW040268R0JNED" 0402 295,1605 r270 bottom value=68
R40 "CRCW040266K5FKED" 0402 447,834 r270 bottom value=66.5k
R41 "CRCW040268R0JNED" 0402 255,1605 r270 bottom value=68
R42 "RG1005P-104-B-T5" 0402 489,834 r90 bottom value=100k
R43 "CRCW0402100KJNED" 0402 115,1025 r0 bottom value=100k
R44 "CRCW040210K0JNED" 0402 115,1075 r180 bottom value=10k
R45 "CRCW040210K0JNED" 0402 115,1325 r180 bottom value=10k
R46 "CRCW040210K0JNED" 0402 115,1275 r180 bottom value=10k
R47 "CRCW040210K0JNED" 0402 115,1225 r180 bottom value=10k
R48 "RG1005P-104-B-T5" 0402 535,1605 r90 bottom value=100k
R49 "CRCW0402200KFKED" 0402 183,987 r270 top value=200k
R50 "ERA-2AEB8662X" 0402 619,896.62 r90 bottom value=86.6k
R51 "CRCW040268R0JNED" 0402 415,1605 r90 bottom value=68
R52 "CRCW040268R0JNED" 0402 115,960 r180 top value=68
R53 "CRCW040268R0JNED" 0402 660,896.62 r90 bottom value=68
R54 "CRCW0402200KFKED" 0402 455,1605 r270 bottom value=200k
R55 "RG1005P-104-B-T5" 0402 160,1070 r0 top value=100k
R56 "CRCW0402200KFKED" 0402 660,799.62 r90 bottom value=200k
R57 "CRCW040268R0JNED" 0402 495,1605 r270 bottom value=68
R58 "CRCW040268R0JNED" 0402 115,1015 r0 top value=68
R59 "CRCW040268R0JNED" 0402 619,799.62 r90 bottom value=68
R60 "CRCW040210K0JNED" 0402 1114.27,2435 r0 bottom value=10k
R61 "ERJ-2RKF4992X" 0402 1260,2515 r90 top value=49.9k
R62 "CRCW12060000Z0EA" 1206 1703.43,1870.08 r270 bottom value=0
R63 "RG1005P-104-B-T5" 0402 1135,2490 r0 top value=100k
R64 "CRCW040251K1FKED" 0402 1184.27,2305 r180 top value=51.1k
R65 "CRCW040251K1FKED" 0402 1259.27,2280 r90 top value=51.1k
R66 "CRCW12060000Z0EA" 1206 1510,195 r180 top value=0
R67 "CRCW12060000Z0EA" 1206 1510,100 r180 top value=0
R68 "CRCW12060000Z0EA" 1206 1080,1945 r270 bottom value=0
R69 "CRCW12060000Z0EA" 1206 740,1945 r270 bottom value=0
R70 "CRCW12060000Z0EA" 1206 855,1945 r270 bottom value=0
R71 "CRCW12060000Z0EA" 1206 970,1945 r270 bottom value=0
R72 "CRCW040210K0JNED" 0402 1160.22,3145 r0 bottom value=10k
R73 "ERJ-2RKF4992X" 0402 1310,3255 r90 top value=49.9k
R74 "RG1005P-104-B-T5" 0402 1185,3225 r0 top value=100k
R75 "CRCW040251K1FKED" 0402 1180,3030 r180 top value=51.1k
R76 "CRCW040251K1FKED" 0402 1250,3000 r90 top value=51.1k
R77 "RT0402BRD0710KL" 0402 1331.48,414.45 r180 top value=10.0k
R78 "CRCW12060000Z0EA" 1206 1521.48,389.45 r0 top value=0
R79 "RT0402BRD0710KL" 0402 1406.48,389.45 r90 top value=10.0k
R80 "CRCW040210K0JNED" 0402 1366.48,164.45 r90 bottom value=10k
R81 "CRCW04020000Z0ED" 0402 1476.48,347.26 r0 bottom value=0
R82 "CRCW0402100KJNED" 0402 1291.48,164.45 r90 bottom value=100k
R83 "ERJ-2RKF9762X" 0402 880.79,373.87 r180 top value=97.6k
R84 "CRCW0402100KJNED" 0402 805.63,377.09 r180 bottom value=100k
R85 "CRCW04020000Z0ED" 0402 1446.48,179.45 r0 bottom value=0
R86 "ERA-2AEB7682X" 0402 800.79,348.87 r90 top value=76.8k
R87 "CRCW0402100KJNED" 0402 1448.79,1945.63 r270 top value=100k
R88 "CRCW0402100KJNED" 0402 2444,397.62 r270 bottom value=100k
R89 "CRCW0402100KJNED" 0402 1349,1774.37 r270 top value=100k
R90 "CRCW040210K0JNED" 0402 2294.37,117.21 r0 bottom value=10k
R91 "CRCW040210K0JNED" 0402 659,601.38 r270 bottom value=10k
R92 "CRCW040210K0JNED" 0402 1162.72,3027 r0 bottom value=10k
R93 "CRCW04020000Z0ED" 0402 1114,2324.83 r180 bottom value=0
R94 "CRCW0402100KJNED" 0402 387,604.37 r270 bottom value=100k
R95 "CRCW040210K0JNED" 0402 477,602.62 r270 bottom value=10k
R96 "CRCW040210K0JNED" 0402 567,601.62 r270 bottom value=10k
R97 "CRCW04020000Z0ED" 0402 282,563.62 r90 bottom value=0
R98 "CRCW04020000Z0ED" 0402 758,602.38 r90 bottom value=0
R99 "CRCW0402100KJNED" 0402 849,604.38 r270 bottom value=100k
R100 "CRCW040210K0JNED" 0402 944,605.38 r270 bottom value=10k
R101 "CRCW04020000Z0ED" 0402 1042.65,604.22 r90 bottom value=0
R102 "CRCW04021M00JNED" 0402 1398.79,1840.63 r90 top value=1.0Meg
R103 "CRCW04021M00JNED" 0402 2394,292.62 r90 bottom value=1.0Meg
R104 "CRCW04021M00JNED" 0402 1299,1669.37 r90 top value=1.0Meg
R105 "CRCW04021M00JNED" 0402 2399.37,67.21 r180 bottom value=1.0Meg
R106 "CRCW04021M00JNED" 0402 609,496.38 r90 bottom value=1.0Meg
R107 "CRCW04021M00JNED" 0402 1267.72,2977 r180 bottom value=1.0Meg
R108 "CRCW04021M00JNED" 0402 1219,2274.83 r180 bottom value=1.0Meg
R109 "CRCW04021M00JNED" 0402 337,499.37 r90 bottom value=1.0Meg
R110 "CRCW04021M00JNED" 0402 427,497.62 r90 bottom value=1.0Meg
R111 "CRCW04021M00JNED" 0402 517,496.62 r90 bottom value=1.0Meg
R112 "CRCW04021M00JNED" 0402 232,458.62 r90 bottom value=1.0Meg
R113 "CRCW04021M00JNED" 0402 708,497.38 r90 bottom value=1.0Meg
R114 "CRCW04021M00JNED" 0402 799,499.38 r90 bottom value=1.0Meg
R115 "CRCW04021M00JNED" 0402 894,490 r90 bottom value=1.0Meg
R116 "CRCW04021M00JNED" 0402 993,482 r90 bottom value=1.0Meg
R117 "CRCW0402240RJNED" 0402 2252.4,975 r0 top value=240
R118 "ERJ-2GEJ361X" 0402 2385,930 r180 top value=360
R119 "CRCW0402150RJNED" 0402 2265,1633 r0 top value=150
R120 "CRCW0402150RJNED" 0402 2269,1875 r0 top value=150
R121 "CRCW0402160RJNED" 0402 2265,2125 r0 top value=160
R122 "CRCW0402150RJNED" 0402 2245,2385 r0 top value=150
R123 "RC0402JR-070RL" 0402 2367.4,1040 r0 bottom value=0
R124 "RC0402JR-070RL" 0402 2371,520 r180 top value=0
R125 "RC0402JR-070RL" 0402 2373.76,1698.21 r0 bottom value=0
R126 "RC0402JR-070RL" 0402 2380,1940 r0 bottom value=0
R127 "RC0402JR-070RL" 0402 2385,2188.21 r0 bottom value=0
R128 "RC0402JR-070RL" 0402 2365,2450 r0 bottom value=0
R129 "CRCW0402150RJNED" 0402 2261.04,2638.58 r0 top value=150
R130 "CRCW0402150RJNED" 0402 2258.62,2895 r0 top value=150
R131 "CRCW0402150RJNED" 0402 2262.24,3163.52 r0 top value=150
R132 "RC0402JR-070RL" 0402 2373.76,2701.79 r0 bottom value=0
R133 "RC0402JR-070RL" 0402 2373.62,2960 r0 bottom value=0
R134 "RC0402JR-070RL" 0402 2367.24,3228.52 r0 bottom value=0
R135 "CRCW12060000Z0EA" 1206 2345,1455 r180 top value=0
R136 "CRCW12060000Z0EA" 1206 2395,1305 r270 top value=0
R137 "CRCW02010000Z0ED" 0201 1944,2131 r270 top value=0
R138 "CRCW02010000Z0ED" 0201 2114,2132 r90 top value=0
R139 "CRCW02010000Z0ED" 0201 1634,1413 r90 top value=0
R140 "CRCW02010000Z0ED" 0201 1678,1397 r90 top value=0
R141 "CRCW02010000Z0ED" 0201 1788,1314 r90 bottom value=0
R142 "CRCW02010000Z0ED" 0201 1817,1314 r90 bottom value=0
R143 "CRCW02010000Z0ED" 0201 1786,1085 r0 top value=0
R144 "CRCW02010000Z0ED" 0201 1786,1057 r0 top value=0
R145 "CRCW02010000Z0ED" 0201 1885,2374 r180 top value=0
R146 "CRCW02010000Z0ED" 0201 1748,698 r90 top value=0
R147 "CRCW02010000Z0ED" 0201 2282,834 r180 top value=0
R148 "CRCW02010000Z0ED" 0201 1811,732 r0 top value=0
R149 "CRCW02010000Z0ED" 0201 2294,746 r90 top value=0
R150 "CRCW02010000Z0ED" 0201 1962,3231 r90 top value=0
R151 "CRCW02010000Z0ED" 0201 1714,368 r0 top value=0
R152 "CRCW02010000Z0ED" 0201 1758,339 r180 top value=0
R153 "CRCW02010000Z0ED" 0201 2287,211 r270 top value=0
R154 "CRCW02010000Z0ED" 0201 2300,170 r180 top value=0
R155 "CRCW040210K0JNED" 0402 600,2475 r270 bottom value=10k
R156 "CRCW0402100KJNED" 0402 829.92,2600 r270 bottom value=100k
R157 "CRCW04021M00JNED" 0402 600,2350 r90 bottom value=1.0Meg
S1 "KST221JLFS" SW_KST221JLFS 1122.64,1785.94 r270 top
S2 "KST221JLFS" SW_KST221JLFS 425,1845 r0 top
U1 "TPS65023BRSBR" RSB0040B 1250.22,920 r270 top
U2 "TPS22920YZPR" YZP0008ADCD 1610,1624.45 r180 top
U3 "TPS65023BRSBR" RSB0040B 355,1245 r180 top
U4 "TPS22920YZPR" YZP0008ADCD 1925.24,278.98 r270 top
U5 "TPS56C215RNNR" RNN0018A 1374.27,2410 r90 top
U6 "TPS22920YZPR" YZP0008ADCD 1730,1875 r90 top
U7 "TPS568215RNNR" RNN0018A 1415.22,3135 r90 top
U8 "TPS62067DSGR" DSG0008A 715.63,307.09 r90 top
U9 "TPS51200DRCR" DRC0010J 1346.48,293.9 r270 bottom
ZZ1 "This Assembly Note is for PCB labels only" AssemblyNoteLabel 105,5948 r0 top
ZZ2 "This Assembly Note will show in the PcbDoc and associated outputs" AssemblyNote 105,5839.11 r0 top
ZZ3 "This Assembly Note will show in the PcbDoc and associated outputs" AssemblyNote 105,5750.56 r0 top
ZZ4 "This Assembly Note will show in the PcbDoc and associated outputs" AssemblyNote 105,5662 r0 top

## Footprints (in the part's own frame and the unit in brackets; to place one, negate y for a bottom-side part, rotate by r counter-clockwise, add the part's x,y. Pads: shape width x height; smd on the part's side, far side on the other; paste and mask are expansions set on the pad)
0201 [mm] "Data from Kemet datasheet CC101_COM dated 7/28/11"
  rect 0.46x0.42 smd mask+0.048: 1(-0.33,0) 2(0.33,0)
  body extent -0.31,-0.16 0.31,0.16, height 0.26
0402 [mm] "0402 from SM-752 data"
  rect 0.8x0.6 smd: 1(-0.6,0) 2(0.6,0)
  silkscreen extent -1.22,-0.52 1.22,0.52, body extent -0.55,-0.3 0.55,0.3, height 0.6
0603 [mm] "0603 from SM-752 data"
  rect 1x0.95 smd: 1(-0.8,0) 2(0.8,0)
  silkscreen extent -1.52,-0.69 1.52,0.69, body extent -0.87,-0.47 0.87,0.47, height 1
0805_HV [mil] "0805 with 30mil clearance between pads"
  rect 50x63 smd: 1(-40,0) 2(40,0)
  silkscreen extent -74,-40 74,40, body extent -43,-29 43,29, height 57
1206 [mm] "1206 from SM-752 data"
  rect 1.3x1.85 smd: 1(-1.45,0) 2(1.45,0)
  silkscreen extent -2.4,-1.21 2.4,1.21, body extent -1.7,-0.9 1.7,0.9, height 1.35
1206_190 [mm] "1206_190"
  rect 1.1x1.6 smd: 1(-1.7,0) 2(1.7,0)
  silkscreen extent -0.9,-1 0.9,1, body extent -1.75,-0.95 1.75,0.95, height 1.9
1210_270 [mm] "1210"
  rect 1.3x2.7 smd: 1(-1.45,0) 2(1.45,0)
  silkscreen extent -2.32,-1.57 2.32,1.57, body extent -1.7,-1.35 1.7,1.35, height 2.7
1210_280 [mm] "SMD, 2-Leads, Body 3.6x2.8mm, Height 2.8mm"
  rect 1.1x2.2 smd: 1(-1.65,0) 2(1.65,0)
  silkscreen extent -0.84,-1.4 0.84,1.4, body extent -1.8,-1.4 1.8,1.4, height 2.8
AssemblyNote [mil] "Assembly Note"
AssemblyNoteLabel [mil] "Assembly Note for PCB Labels"
CONN_1725656 [mm] "Phoenix Contact"
  rect 1.8x1.8 hole 1.1: 1(-1.27,0)
  round 1.8 hole 1.1: 2(1.27,0)
  round 1.1 hole 1.1 unplated: MH1(-1.275,-2.54) MH2(1.27,-2.54)
  silkscreen extent -3.08,-3.37 3.08,3.37, body extent -2.77,-3.1 2.77,3.1, height 8.52
CUI_PJ-058B [mm] "Connector,2.5 mm Center Pin, TH"
  oval 4.1x1.6 hole 1 slot 3.5 at 0 deg: 1(0,14.5)
  oval 3.6x1.6 hole 1 slot 3 at 0 deg: 2(0,8.5)
  oval 1.6x3.6 hole 1 slot 3 at 90 deg: 3(4.7,11.5)
  round 1.524 hole 2.2 unplated: MH-1(0,4)
  silkscreen extent -4.5,0.3 4.5,15.2, body extent -4.5,0 4.9,15.2, height 11
DPAK [mm] "D-PAK, 3-Pads, Body 6.22x6.73mm (max), TO-252AA using nominal STEP model"
  rrect6% 2.6x1.6 smd: 1(-3.4,2.28) 3(-3.4,-2.28)
  rrect2% 6.2x5.8 smd paste-2.9: 4(3.4,0)
  silkscreen extent -4.5,-3.3 4.7,3.28, body extent -3.86,-3.29 5.84,3.29, height 2.48
DRC0010J [mm] "SON, 10-Leads, Body 3x3mm, Pitch 0.5mm, Thermal Pad 2.4x1.65mm, TI Recommended"
  rrect40% 0.6x0.25 smd: 1(-1.4,1) 2(-1.4,0.5) 3(-1.4,0) 4(-1.4,-0.5) 5(-1.4,-1) 6(1.4,-1) 7(1.4,-0.5) 8(1.4,0) 9(1.4,0.5) 10(1.4,1)
  rrect40% 0.25x0.34 on Bottom Paste: 11(-0.25,-1.53) 11(-0.25,1.53) 11(0.25,-1.53) 11(0.25,1.53)
  rrect9% 1.5x1.06 on Bottom Paste: 11(0,-0.63) 11(0,0.63)
  rrect12% 1.65x2.4 smd paste-1 mask-2: 11(0,0)
  Top Layer region: -0.775,-1.25 -0.425,-1.25 -0.425,-1.65 -0.417,-1.688 -0.396,-1.721 -0.363,-1.742 -0.325,-1.75 -0.325,-1.75 -0.325,-1.75 -0.175,-1.75 -0.175,-1.75 -0.137,-1.742 -0.104,-1.721 -0.083,-1.688 -0.075,-1.65 -0.075,-1.65 -0.075,-1.25 0.075,-1.25 0.075,-1.65 0.083,-1.688 0.104,-1.721 0.137,-1.742 0.175,-1.75 0.175,-1.75 0.175,-1.75 0.325,-1.75 0.325,-1.75 0.363,-1.742 0.396,-1.721 0.417,-1.688 0.425,-1.65 0.425,-1.65 0.425,-1.25 0.775,-1.25 0.813,-1.242 0.846,-1.221 0.867,-1.188 0.875,-1.15 0.875,-1.15 0.875,1.15 0.867,1.188 0.846,1.221 0.813,1.242 0.775,1.25 0.775,1.25 0.425,1.25 0.425,1.65 0.417,1.688 0.396,1.721 0.363,1.742 0.325,1.75 0.325,1.75 0.175,1.75 0.137,1.742 0.104,1.721 0.083,1.688 0.075,1.65 0.075,1.65 0.075,1.25 -0.075,1.25 -0.075,1.65 -0.083,1.688 -0.104,1.721 -0.137,1.742 -0.175,1.75 -0.175,1.75 -0.325,1.75 -0.363,1.742 -0.396,1.721 -0.417,1.688 -0.425,1.65 -0.425,1.65 -0.425,1.25 -0.775,1.25 -0.813,1.242 -0.846,1.221 -0.867,1.188 -0.875,1.15 -0.875,1.15 -0.875,-1.15 -0.867,-1.188 -0.846,-1.221 -0.813,-1.242 -0.775,-1.25
  silkscreen extent -1.63,-1.63 1.63,1.63, body extent -1.5,-1.5 1.5,1.5, height 0.77
DSG0008A [mm] "SON, 8-Leads, Body 2x2mm, Pitch 0.5mm, Thermal Pad 1.6x0.9mm, TI Recommended"
  rrect40% 0.5x0.25 smd: 1(-0.95,0.75) 2(-0.95,0.25) 3(-0.95,-0.25) 4(-0.95,-0.75) 5(0.95,-0.75) 6(0.95,-0.25) 7(0.95,0.25) 8(0.95,0.75)
  rrect14% 0.9x0.7 on Top Paste: 9(0,0.45) 9(0,-0.45)
  rrect11% 0.9x1.6 smd paste-0.45: 9(0,0)
  silkscreen extent -1.07,-1.15 1.07,1.15, body extent -1,-1 1,1, height 0.77
FCC_disclaimer [mil]
Fiducial10-20 [mm]
  round 1 smd mask+0.5: 1(0,0)
  Top Layer keep-out circle w1.178: c0,0 r0.5
IHLP-1212AB [mm] "VISHAY"
  rect 1.5x1.2 smd: 1(-1.35,0) 2(1.35,0)
  silkscreen extent -1.65,-1.65 1.65,1.65, body extent -1.8,-1.6 1.8,1.6, height 1.6
IHLP-2020BZ [mm] "Vishay Dale recommended land pattern.  Document 34261 rev 12-Sept-13"
  rect 1.915x2.79 smd: 1(-2.037,0) 2(2.037,0)
  silkscreen extent -2.9,-2.7 2.9,2.7, body extent -2.87,-2.72 2.87,2.72, height 2
IHLP-2525CZ [mm] "Vishay Dale recommended land pattern.  Document 34190 rev 10-Aug-06"
  rect 1.83x3.43 smd: 1(-2.77,0) 2(2.77,0)
  silkscreen extent -3.5,-3.3 3.5,3.3, body extent -3.62,-3.36 3.62,3.36, height 3
Keystone_1902C [mil] "Hex Standoff, 4-40 threaded, nylon"
  round 1 on Mech4: 0(0,0)
  body extent -145,-126 146,126, height 501
LED_LTST-C170 [mm] "LITE-ON"
  rect 1.2x1.2 smd: 1(-1.05,0) 2(1.05,0)
  silkscreen extent -1.6,-1 2.2,1, body extent -1.05,-0.67 1.05,0.67, height 1.1
LED_LTST-C190 [mm] "Lite-On"
  rect 0.8x0.8 smd: 1(-0.75,0) 2(0.75,0)
  silkscreen extent -1.1,-0.8 1.8,0.8, body extent -0.85,-0.45 0.85,0.45, height 0.9
LED_LTST-C190_G [mm] "Lite-On"
  rect 0.8x0.8 smd: 1(-0.75,0) 2(0.75,0)
  silkscreen extent 1.37,-0.5 1.75,0.5, body extent -0.85,-0.45 0.85,0.45, height 0.9
LNJ037X8_WHITE [mm] "Panasonic"
  rect 0.7x0.8 smd: 1(-0.775,0) 2(0.775,0)
  silkscreen extent -1.82,-0.75 1.07,0.77, body extent -0.85,-0.45 0.85,0.45, height 0.25
Mill-Max_800-10-006-10-001000 [mm] "Mill-Max"
  rect 1.5x1.5 hole 0.85: 1(-6.35,0)
  round 1.5 hole 0.85: 2(-3.81,0) 3(-1.27,0) 4(1.27,0) 5(3.81,0) 6(6.35,0)
  silkscreen extent -7.62,-1.27 7.62,1.78, body extent -7.62,-1.27 7.62,1.27, height 8.13
"NY PMS 440 0025 PH" [mm] "4-40 nylon screw and mounting hole"
  round 8 hole 3.2: 1(0,0)
  body extent -3.3,-3.3 3.3,3.3, height 2.69
Pb-Free_Overlay_Small [mil]
  silkscreen extent -46,-46 46,46
RNN0018A [mm] "SMD, 18-Leads, Body 3.5x3.5mm"
  rrect40% 0.6x0.25 smd paste+0 mask+0.05: 1(-1.65,0.925) 12(1.65,0.925)
  rrect40% 1.25x0.5 smd paste-2 mask-0.05: 2(-1.375,0.35) 11(1.375,0.35)
  rrect57% 1.25x0.35 smd paste-0.05 mask-0.05: 3(-1.375,-0.3) 4(-1.375,-0.85) 5(-1.375,-1.4) 8(1.375,-1.4) 9(1.375,-0.85) 10(1.375,-0.3)
  rrect50% 0.4x2.7 smd paste-3 mask-0.05: 6(-0.3,-0.65) 7(0.3,-0.65)
  rrect40% 0.25x0.6 smd paste+0 mask+0.05: 13(1.25,1.65) 14(0.75,1.65) 15(0.25,1.65) 16(-0.25,1.65) 17(-0.75,1.65) 18(-1.25,1.65)
  rrect28% 1.15x0.36 on Top Paste: ""(-1.375,0.35) ""(1.375,0.35)
  rrect33% 0.3x0.733 on Top Paste: ""(-0.3,0.282) ""(-0.3,-0.651) ""(-0.3,-1.585) ""(0.3,0.282) ""(0.3,-0.651) ""(0.3,-1.585)
  silkscreen extent -1.75,-1.95 1.75,1.75, body extent -1.75,-1.75 1.75,1.75, height 1.01
RSB0040B [mm] "QFN, 40-Leads, Body 5x5mm, Pitch 0.4mm, Thermal Pad 3.5x3.5mm, TI Recommended"
  oval 0.6x0.2 smd: 1(-2.45,1.8) 2(-2.45,1.4) 3(-2.45,1) 4(-2.45,0.6) 5(-2.45,0.2) 6(-2.45,-0.2) 7(-2.45,-0.6) 8(-2.45,-1) 9(-2.45,-1.4) 10(-2.45,-1.8) 21(2.45,-1.8) 22(2.45,-1.4) 23(2.45,-1) 24(2.45,-0.6) 25(2.45,-0.2) 26(2.45,0.2) 27(2.45,0.6) 28(2.45,1) 29(2.45,1.4) 30(2.45,1.8)
  oval 0.2x0.6 smd: 11(-1.8,-2.45) 12(-1.4,-2.45) 13(-1,-2.45) 14(-0.6,-2.45) 15(-0.2,-2.45) 16(0.2,-2.45) 17(0.6,-2.45) 18(1,-2.45) 19(1.4,-2.45) 20(1.8,-2.45) 31(1.8,2.45) 32(1.4,2.45) 33(1,2.45) 34(0.6,2.45) 35(0.2,2.45) 36(-0.2,2.45) 37(-0.6,2.45) 38(-1,2.45) 39(-1.4,2.45) 40(-1.8,2.45)
  rect 3.5x3.5 smd paste-1.75: 41(0,0)
  silkscreen extent -2.72,-2.73 2.72,2.73, body extent -2.57,-2.57 2.58,2.58, height 0.81
Samtec_BSE-060-01-L-D-A [mm] "Socket Assembly, 0.8mm, 60x2, SMT"
  rrect24% 0.41x2.273 smd: 1(-23.6,-2.863) 2(-23.6,2.864) 3(-22.8,-2.863) 4(-22.8,2.864) 5(-22,-2.863) 6(-22,2.864) 7(-21.2,-2.863) 8(-21.2,2.864) 9(-20.4,-2.863) 10(-20.4,2.864) 11(-19.6,-2.863) 12(-19.6,2.864) 13(-18.8,-2.863) 14(-18.8,2.864) 15(-18,-2.863) 16(-18,2.864) 17(-17.2,-2.863) 18(-17.2,2.864) 19(-16.4,-2.863) 20(-16.4,2.864) 21(-15.6,-2.863) 22(-15.6,2.864) 23(-14.8,-2.863) 24(-14.8,2.864) 25(-14,-2.863) 26(-14,2.864) 27(-13.2,-2.863) 28(-13.2,2.864) 29(-12.4,-2.863) 30(-12.4,2.864) 31(-11.6,-2.863) 32(-11.6,2.864) 33(-10.8,-2.863) 34(-10.8,2.864) 35(-10,-2.863) 36(-10,2.864) 37(-9.2,-2.863) 38(-9.2,2.864) 39(-8.4,-2.863) 40(-8.4,2.864) 41(-7.6,-2.863) 42(-7.6,2.864) 43(-6.8,-2.863) 44(-6.8,2.864) 45(-6,-2.863) 46(-6,2.864) 47(-5.2,-2.863) 48(-5.2,2.864) 49(-4.4,-2.863) 50(-4.4,2.864) 51(-3.6,-2.863) 52(-3.6,2.864) 53(-2.8,-2.863) 54(-2.8,2.864) 55(-2,-2.863) 56(-2,2.864) 57(-1.2,-2.863) 58(-1.2,2.864) 59(-0.4,-2.863) 60(-0.4,2.864) 61(0.4,-2.863) 62(0.4,2.864) 63(1.2,-2.863) 64(1.2,2.864) 65(2,-2.863) 66(2,2.864) 67(2.8,-2.863) 68(2.8,2.864) 69(3.6,-2.863) 70(3.6,2.864) 71(4.4,-2.863) 72(4.4,2.864) 73(5.2,-2.863) 74(5.2,2.864) 75(6,-2.863) 76(6,2.864) 77(6.8,-2.863) 78(6.8,2.864) 79(7.6,-2.863) 80(7.6,2.864) 81(8.4,-2.863) 82(8.4,2.864) 83(9.2,-2.863) 84(9.2,2.864) 85(10,-2.863) 86(10,2.864) 87(10.8,-2.863) 88(10.8,2.864) 89(11.6,-2.863) 90(11.6,2.864) 91(12.4,-2.863) 92(12.4,2.864) 93(13.2,-2.863) 94(13.2,2.864) 95(14,-2.863) 96(14,2.864) 97(14.8,-2.863) 98(14.8,2.864) 99(15.6,-2.863) 100(15.6,2.864) 101(16.4,-2.863) 102(16.4,2.864) 103(17.2,-2.863) 104(17.2,2.864) 105(18,-2.863) 106(18,2.864) 107(18.8,-2.863) 108(18.8,2.864) 109(19.6,-2.863) 110(19.6,2.864) 111(20.4,-2.863) 112(20.4,2.864) 113(21.2,-2.863) 114(21.2,2.864) 115(22,-2.863) 116(22,2.864) 117(22.8,-2.863) 118(22.8,2.864) 119(23.6,-2.863) 120(23.6,2.864)
  round 0.7 hole 1.02 unplated mask+0.102: MH-1(-26.065,2.67) MH-2(26.065,2.67)
  silkscreen extent -26.64,-3.62 26.64,3.62, body extent -26.64,-3.75 26.64,3.75, height 3.25
Samtec_MPS-04-7_70-01-x-V [mm] "Receptacle, 5mm, 4x1, TH"
  round 1.56 hole 1.04: 1(-2.73,6.56) 1(-0.19,6.56) 1(-0.19,8.44) 1(2.35,6.56) 1(2.35,8.44) 2(-2.73,1.56) 2(-2.73,3.44) 2(-0.19,1.56) 2(-0.19,3.44) 2(2.35,1.56) 2(2.35,3.44) 3(-2.73,-3.44) 3(-2.73,-1.56) 3(-0.19,-3.44) 3(-0.19,-1.56) 3(2.35,-3.44) 3(2.35,-1.56) 4(-2.73,-8.44) 4(-2.73,-6.56) 4(-0.19,-8.44) 4(-0.19,-6.56) 4(2.35,-8.44) 4(2.35,-6.56)
  rrect50% 1.56x1.56 hole 1.04: 1(-2.73,8.44)
  round 0.89 hole 1.19 unplated mask+0.102: MH1(2.73,11.32) MH2(2.73,-11.32)
  silkscreen extent -5.7,-13.77 4.89,13.78, body extent -5.27,-13.77 4.89,13.78, height 10.09
SOT-23 [mm] "SOT23, 3-Leads, Body 2.9x1.3mm, Pitch 0.95mm, Lead Span 2.5mm, IPC Medium Density"
  rrect50% 1x0.6 smd: 1(-1.2,0.95) 2(-1.2,-0.95) 3(1.2,0)
  silkscreen extent -1.62,-1.5 0.7,1.5, body extent -1.16,-1.45 1.21,1.45, height 1
SW_KST221JLFS [mm] "C&K"
  rect 2.8x1 smd: 1(-2.9,2) 2(2.9,2) 3(-2.9,-2) 4(2.9,-2)
  body extent -3.25,-3.25 3.25,3.25, height 5
TFM252012 [mm] "SMD, 2-Leads, Body 2.5x2mm"
  rect 0.7x2 smd: 1(-1.1,0) 2(1.1,0)
  silkscreen extent -0.45,-1.1 0.45,1.1, body extent -1.35,-1.1 1.35,1.1, height 1.2
TI_Stacked_Overlay_Small [mil]
  silkscreen extent -418,-98 418,98
VLMR334_Red [mm] "SMD, 2-Leads, Body 3x2.8mm"
  rrect6% 1.6x2.6 smd: 1(-1.4,0) 2(1.4,0)
  silkscreen extent -2.2,-1.75 2.7,1.75, body extent -1.75,-1.4 1.75,1.4, height 1.65
YZP0008ADCD [mm] "BGA, 8-Leads, Body 1.9x0.9mm, Pitch 0.5mm"
  round 0.23 smd paste-0.12: A1(-0.25,0.75) A2(0.25,0.75) B1(-0.25,0.25) B2(0.25,0.25) C1(-0.25,-0.25) C2(0.25,-0.25) D1(-0.25,-0.75) D2(0.25,-0.75)
  silkscreen extent -0.6,-1.1 0.6,1.1, body extent -0.46,-0.96 0.46,0.96, height 0.51

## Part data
C1 C14 C18 C26 C36 C43 C95: library part CMP-0006629-2, "CAP, CERM, 0.1 uF, 10 V, +/- 10%, X7R, 0402", Cap_Case=0402, Manufacturer=MuRata, Supplier Part Number 1=GRM155R71A104KA01D-ND, TempCo=X7R, Tolerance_%=10%, Value1=Unknown, Value2=10V, ValueDisplayed=0.1uF
C2 C9 C15 C19 C23 C24 C27 C37 C40 C44 C48 C49 C64: library part CMP-0007370-3, "CAP, CERM, 2.2 uF, 10 V, +/- 10%, X7R, 0603", Cap_Case=0603, Manufacturer=MuRata, Supplier Part Number 1=490-4520-1-ND, TempCo=X7R, Tolerance_%=10%, Value1="0.009 ohm", Value2=10V, ValueDisplayed=2.2uF
C3 C4 C5 C6 C16 C17 C20 C21 C28 C29 C30 C31 C38 C39 C45 C46 C88 C89: library part CMP-0007890-2, "CAP, CERM, 22 uF, 10 V, +/- 20%, X7S, 0805", Cap_Case=0805, Manufacturer=TDK, Supplier Part Number 1=445-14560-1-ND, TempCo=X7S, Tolerance_%=20%, Value1="0.00205 ohm", Value2=10V, ValueDisplayed=22uF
